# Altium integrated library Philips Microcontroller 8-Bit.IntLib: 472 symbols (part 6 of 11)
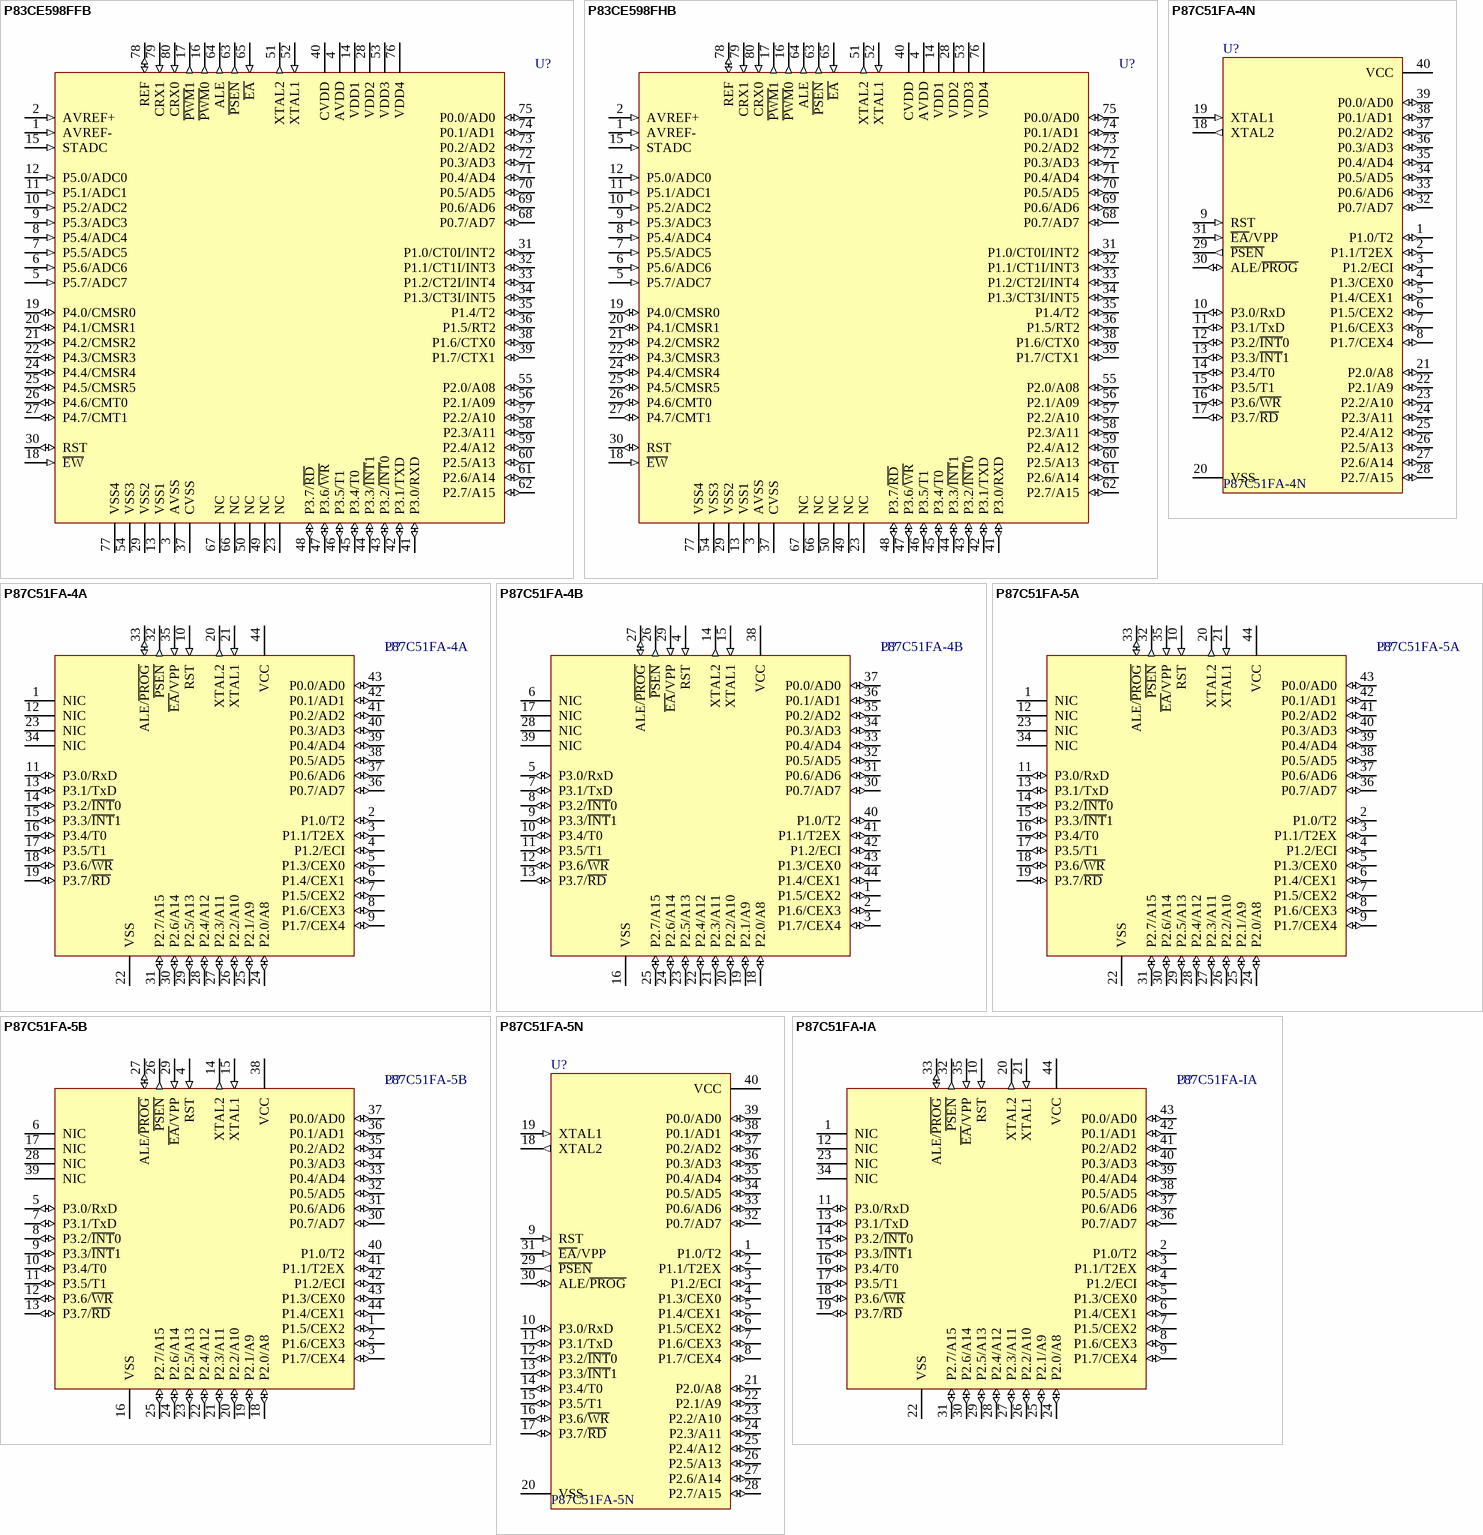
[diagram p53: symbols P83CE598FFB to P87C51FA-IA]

## P87C51FA-4A
designator U?
80C51 8-Bit Microcontroller Family: 256 B RAM, 8 kB OTP, 2.7V-5.5V, Low Power, High Speed
footprint SOT187-2_N (Leaded Chip Carrier, 44-Leads, Body 16.6x16.6mm, Pitch 1.27mm, IPC Medium Density)
footprint SOT187-2_L (Leaded Chip Carrier, 44-Leads, Body 16.6x16.6mm, Pitch 1.27mm, IPC High Density)
footprint SOT187-2_M (Leaded Chip Carrier, 44-Leads, Body 16.6x16.6mm, Pitch 1.27mm, IPC Low Density)
pins: 1 NIC, 2 P1.0/T2 (io), 3 P1.1/T2EX (io), 4 P1.2/ECI (io), 5 P1.3/CEX0 (io), 6 P1.4/CEX1 (io), 7 P1.5/CEX2 (io), 8 P1.6/CEX3 (io), 9 P1.7/CEX4 (io), 10 RST (in), 11 P3.0/RxD (io), 12 NIC, 13 P3.1/TxD (io), 14 P3.2/~{INT}0 (io), 15 P3.3/~{INT}1 (io), 16 P3.4/T0 (io), 17 P3.5/T1 (io), 18 P3.6/~{WR} (io), 19 P3.7/~{RD} (io), 20 XTAL2 (out), 21 XTAL1 (in), 22 VSS (power), 23 NIC, 24 P2.0/A8 (io), 25 P2.1/A9 (io), 26 P2.2/A10 (io), 27 P2.3/A11 (io), 28 P2.4/A12 (io), 29 P2.5/A13 (io), 30 P2.6/A14 (io), 31 P2.7/A15 (io), 32 ~{PSEN} (out), 33 ALE/~{PROG} (io), 34 NIC, 35 ~{EA}/VPP (in), 36 P0.7/AD7 (io), 37 P0.6/AD6 (io), 38 P0.5/AD5 (io), 39 P0.4/AD4 (io), 40 P0.3/AD3 (io), 41 P0.2/AD2 (io), 42 P0.1/AD1 (io), 43 P0.0/AD0 (io), 44 VCC (power)

## P87C51FA-4B
designator U?
80C51 8-Bit Microcontroller Family: 256 B RAM, 8 kB OTP, 2.7V-5.5V, Low Power, High Speed
footprint SOT307-2_N (QFP, 44-Leads, Body 10x10mm, Pitch 0.8mm, IPC Medium Density)
footprint SOT307-2_L (QFP, 44-Leads, Body 10x10mm, Pitch 0.8mm, IPC High Density)
footprint SOT307-2_M (QFP, 44-Leads, Body 10x10mm, Pitch 0.8mm, IPC Low Density)
pins: 1 P1.5/CEX2 (io), 2 P1.6/CEX3 (io), 3 P1.7/CEX4 (io), 4 RST (in), 5 P3.0/RxD (io), 6 NIC, 7 P3.1/TxD (io), 8 P3.2/~{INT}0 (io), 9 P3.3/~{INT}1 (io), 10 P3.4/T0 (io), 11 P3.5/T1 (io), 12 P3.6/~{WR} (io), 13 P3.7/~{RD} (io), 14 XTAL2 (out), 15 XTAL1 (in), 16 VSS (power), 17 NIC, 18 P2.0/A8 (io), 19 P2.1/A9 (io), 20 P2.2/A10 (io), 21 P2.3/A11 (io), 22 P2.4/A12 (io), 23 P2.5/A13 (io), 24 P2.6/A14 (io), 25 P2.7/A15 (io), 26 ~{PSEN} (out), 27 ALE/~{PROG} (io), 28 NIC, 29 ~{EA}/VPP (in), 30 P0.7/AD7 (io), 31 P0.6/AD6 (io), 32 P0.5/AD5 (io), 33 P0.4/AD4 (io), 34 P0.3/AD3 (io), 35 P0.2/AD2 (io), 36 P0.1/AD1 (io), 37 P0.0/AD0 (io), 38 VCC (power), 39 NIC, 40 P1.0/T2 (io), 41 P1.1/T2EX (io), 42 P1.2/ECI (io), 43 P1.3/CEX0 (io), 44 P1.4/CEX1 (io)

## P87C51FA-4N
designator U?
80C51 8-Bit Microcontroller Family: 256 B RAM, 8 kB OTP, 2.7V-5.5V, Low Power, High Speed
footprint SOT129-1 (DIP, Plastic; 40 Leads; Row Spacing 15.24 mm; Pitch 2.54 mm)
pins: 1 P1.0/T2 (io), 2 P1.1/T2EX (io), 3 P1.2/ECI (io), 4 P1.3/CEX0 (io), 5 P1.4/CEX1 (io), 6 P1.5/CEX2 (io), 7 P1.6/CEX3 (io), 8 P1.7/CEX4 (io), 9 RST (in), 10 P3.0/RxD (io), 11 P3.1/TxD (io), 12 P3.2/~{INT}0 (io), 13 P3.3/~{INT}1 (io), 14 P3.4/T0 (io), 15 P3.5/T1 (io), 16 P3.6/~{WR} (io), 17 P3.7/~{RD} (io), 18 XTAL2 (out), 19 XTAL1 (in), 20 VSS (power), 21 P2.0/A8 (io), 22 P2.1/A9 (io), 23 P2.2/A10 (io), 24 P2.3/A11 (io), 25 P2.4/A12 (io), 26 P2.5/A13 (io), 27 P2.6/A14 (io), 28 P2.7/A15 (io), 29 ~{PSEN} (out), 30 ALE/~{PROG} (io), 31 ~{EA}/VPP (in), 32 P0.7/AD7 (io), 33 P0.6/AD6 (io), 34 P0.5/AD5 (io), 35 P0.4/AD4 (io), 36 P0.3/AD3 (io), 37 P0.2/AD2 (io), 38 P0.1/AD1 (io), 39 P0.0/AD0 (io), 40 VCC (power)

## P87C51FA-5A
designator U?
80C51 8-Bit Microcontroller Family: 256 B RAM, 8 kB OTP, 2.7V-5.5V, Low Power, High Speed
footprint SOT187-2_N (Leaded Chip Carrier, 44-Leads, Body 16.6x16.6mm, Pitch 1.27mm, IPC Medium Density)
footprint SOT187-2_L (Leaded Chip Carrier, 44-Leads, Body 16.6x16.6mm, Pitch 1.27mm, IPC High Density)
footprint SOT187-2_M (Leaded Chip Carrier, 44-Leads, Body 16.6x16.6mm, Pitch 1.27mm, IPC Low Density)
pins: 1 NIC, 2 P1.0/T2 (io), 3 P1.1/T2EX (io), 4 P1.2/ECI (io), 5 P1.3/CEX0 (io), 6 P1.4/CEX1 (io), 7 P1.5/CEX2 (io), 8 P1.6/CEX3 (io), 9 P1.7/CEX4 (io), 10 RST (in), 11 P3.0/RxD (io), 12 NIC, 13 P3.1/TxD (io), 14 P3.2/~{INT}0 (io), 15 P3.3/~{INT}1 (io), 16 P3.4/T0 (io), 17 P3.5/T1 (io), 18 P3.6/~{WR} (io), 19 P3.7/~{RD} (io), 20 XTAL2 (out), 21 XTAL1 (in), 22 VSS (power), 23 NIC, 24 P2.0/A8 (io), 25 P2.1/A9 (io), 26 P2.2/A10 (io), 27 P2.3/A11 (io), 28 P2.4/A12 (io), 29 P2.5/A13 (io), 30 P2.6/A14 (io), 31 P2.7/A15 (io), 32 ~{PSEN} (out), 33 ALE/~{PROG} (io), 34 NIC, 35 ~{EA}/VPP (in), 36 P0.7/AD7 (io), 37 P0.6/AD6 (io), 38 P0.5/AD5 (io), 39 P0.4/AD4 (io), 40 P0.3/AD3 (io), 41 P0.2/AD2 (io), 42 P0.1/AD1 (io), 43 P0.0/AD0 (io), 44 VCC (power)

## P87C51FA-5B
designator U?
80C51 8-Bit Microcontroller Family: 256 B RAM, 8 kB OTP, 2.7V-5.5V, Low Power, High Speed
footprint SOT307-2_N (QFP, 44-Leads, Body 10x10mm, Pitch 0.8mm, IPC Medium Density)
footprint SOT307-2_L (QFP, 44-Leads, Body 10x10mm, Pitch 0.8mm, IPC High Density)
footprint SOT307-2_M (QFP, 44-Leads, Body 10x10mm, Pitch 0.8mm, IPC Low Density)
pins: 1 P1.5/CEX2 (io), 2 P1.6/CEX3 (io), 3 P1.7/CEX4 (io), 4 RST (in), 5 P3.0/RxD (io), 6 NIC, 7 P3.1/TxD (io), 8 P3.2/~{INT}0 (io), 9 P3.3/~{INT}1 (io), 10 P3.4/T0 (io), 11 P3.5/T1 (io), 12 P3.6/~{WR} (io), 13 P3.7/~{RD} (io), 14 XTAL2 (out), 15 XTAL1 (in), 16 VSS (power), 17 NIC, 18 P2.0/A8 (io), 19 P2.1/A9 (io), 20 P2.2/A10 (io), 21 P2.3/A11 (io), 22 P2.4/A12 (io), 23 P2.5/A13 (io), 24 P2.6/A14 (io), 25 P2.7/A15 (io), 26 ~{PSEN} (out), 27 ALE/~{PROG} (io), 28 NIC, 29 ~{EA}/VPP (in), 30 P0.7/AD7 (io), 31 P0.6/AD6 (io), 32 P0.5/AD5 (io), 33 P0.4/AD4 (io), 34 P0.3/AD3 (io), 35 P0.2/AD2 (io), 36 P0.1/AD1 (io), 37 P0.0/AD0 (io), 38 VCC (power), 39 NIC, 40 P1.0/T2 (io), 41 P1.1/T2EX (io), 42 P1.2/ECI (io), 43 P1.3/CEX0 (io), 44 P1.4/CEX1 (io)

## P87C51FA-5N
designator U?
80C51 8-Bit Microcontroller Family: 256 B RAM, 8 kB OTP, 2.7V-5.5V, Low Power, High Speed
footprint SOT129-1 (DIP, Plastic; 40 Leads; Row Spacing 15.24 mm; Pitch 2.54 mm)
pins: 1 P1.0/T2 (io), 2 P1.1/T2EX (io), 3 P1.2/ECI (io), 4 P1.3/CEX0 (io), 5 P1.4/CEX1 (io), 6 P1.5/CEX2 (io), 7 P1.6/CEX3 (io), 8 P1.7/CEX4 (io), 9 RST (in), 10 P3.0/RxD (io), 11 P3.1/TxD (io), 12 P3.2/~{INT}0 (io), 13 P3.3/~{INT}1 (io), 14 P3.4/T0 (io), 15 P3.5/T1 (io), 16 P3.6/~{WR} (io), 17 P3.7/~{RD} (io), 18 XTAL2 (out), 19 XTAL1 (in), 20 VSS (power), 21 P2.0/A8 (io), 22 P2.1/A9 (io), 23 P2.2/A10 (io), 24 P2.3/A11 (io), 25 P2.4/A12 (io), 26 P2.5/A13 (io), 27 P2.6/A14 (io), 28 P2.7/A15 (io), 29 ~{PSEN} (out), 30 ALE/~{PROG} (io), 31 ~{EA}/VPP (in), 32 P0.7/AD7 (io), 33 P0.6/AD6 (io), 34 P0.5/AD5 (io), 35 P0.4/AD4 (io), 36 P0.3/AD3 (io), 37 P0.2/AD2 (io), 38 P0.1/AD1 (io), 39 P0.0/AD0 (io), 40 VCC (power)

## P87C51FA-IA
designator U?
80C51 8-Bit Microcontroller Family: 256 B RAM, 8 kB OTP, 5V, Low Power, High Speed
footprint SOT187-2_N (Leaded Chip Carrier, 44-Leads, Body 16.6x16.6mm, Pitch 1.27mm, IPC Medium Density)
footprint SOT187-2_L (Leaded Chip Carrier, 44-Leads, Body 16.6x16.6mm, Pitch 1.27mm, IPC High Density)
footprint SOT187-2_M (Leaded Chip Carrier, 44-Leads, Body 16.6x16.6mm, Pitch 1.27mm, IPC Low Density)
pins: 1 NIC, 2 P1.0/T2 (io), 3 P1.1/T2EX (io), 4 P1.2/ECI (io), 5 P1.3/CEX0 (io), 6 P1.4/CEX1 (io), 7 P1.5/CEX2 (io), 8 P1.6/CEX3 (io), 9 P1.7/CEX4 (io), 10 RST (in), 11 P3.0/RxD (io), 12 NIC, 13 P3.1/TxD (io), 14 P3.2/~{INT}0 (io), 15 P3.3/~{INT}1 (io), 16 P3.4/T0 (io), 17 P3.5/T1 (io), 18 P3.6/~{WR} (io), 19 P3.7/~{RD} (io), 20 XTAL2 (out), 21 XTAL1 (in), 22 VSS (power), 23 NIC, 24 P2.0/A8 (io), 25 P2.1/A9 (io), 26 P2.2/A10 (io), 27 P2.3/A11 (io), 28 P2.4/A12 (io), 29 P2.5/A13 (io), 30 P2.6/A14 (io), 31 P2.7/A15 (io), 32 ~{PSEN} (out), 33 ALE/~{PROG} (io), 34 NIC, 35 ~{EA}/VPP (in), 36 P0.7/AD7 (io), 37 P0.6/AD6 (io), 38 P0.5/AD5 (io), 39 P0.4/AD4 (io), 40 P0.3/AD3 (io), 41 P0.2/AD2 (io), 42 P0.1/AD1 (io), 43 P0.0/AD0 (io), 44 VCC (power)

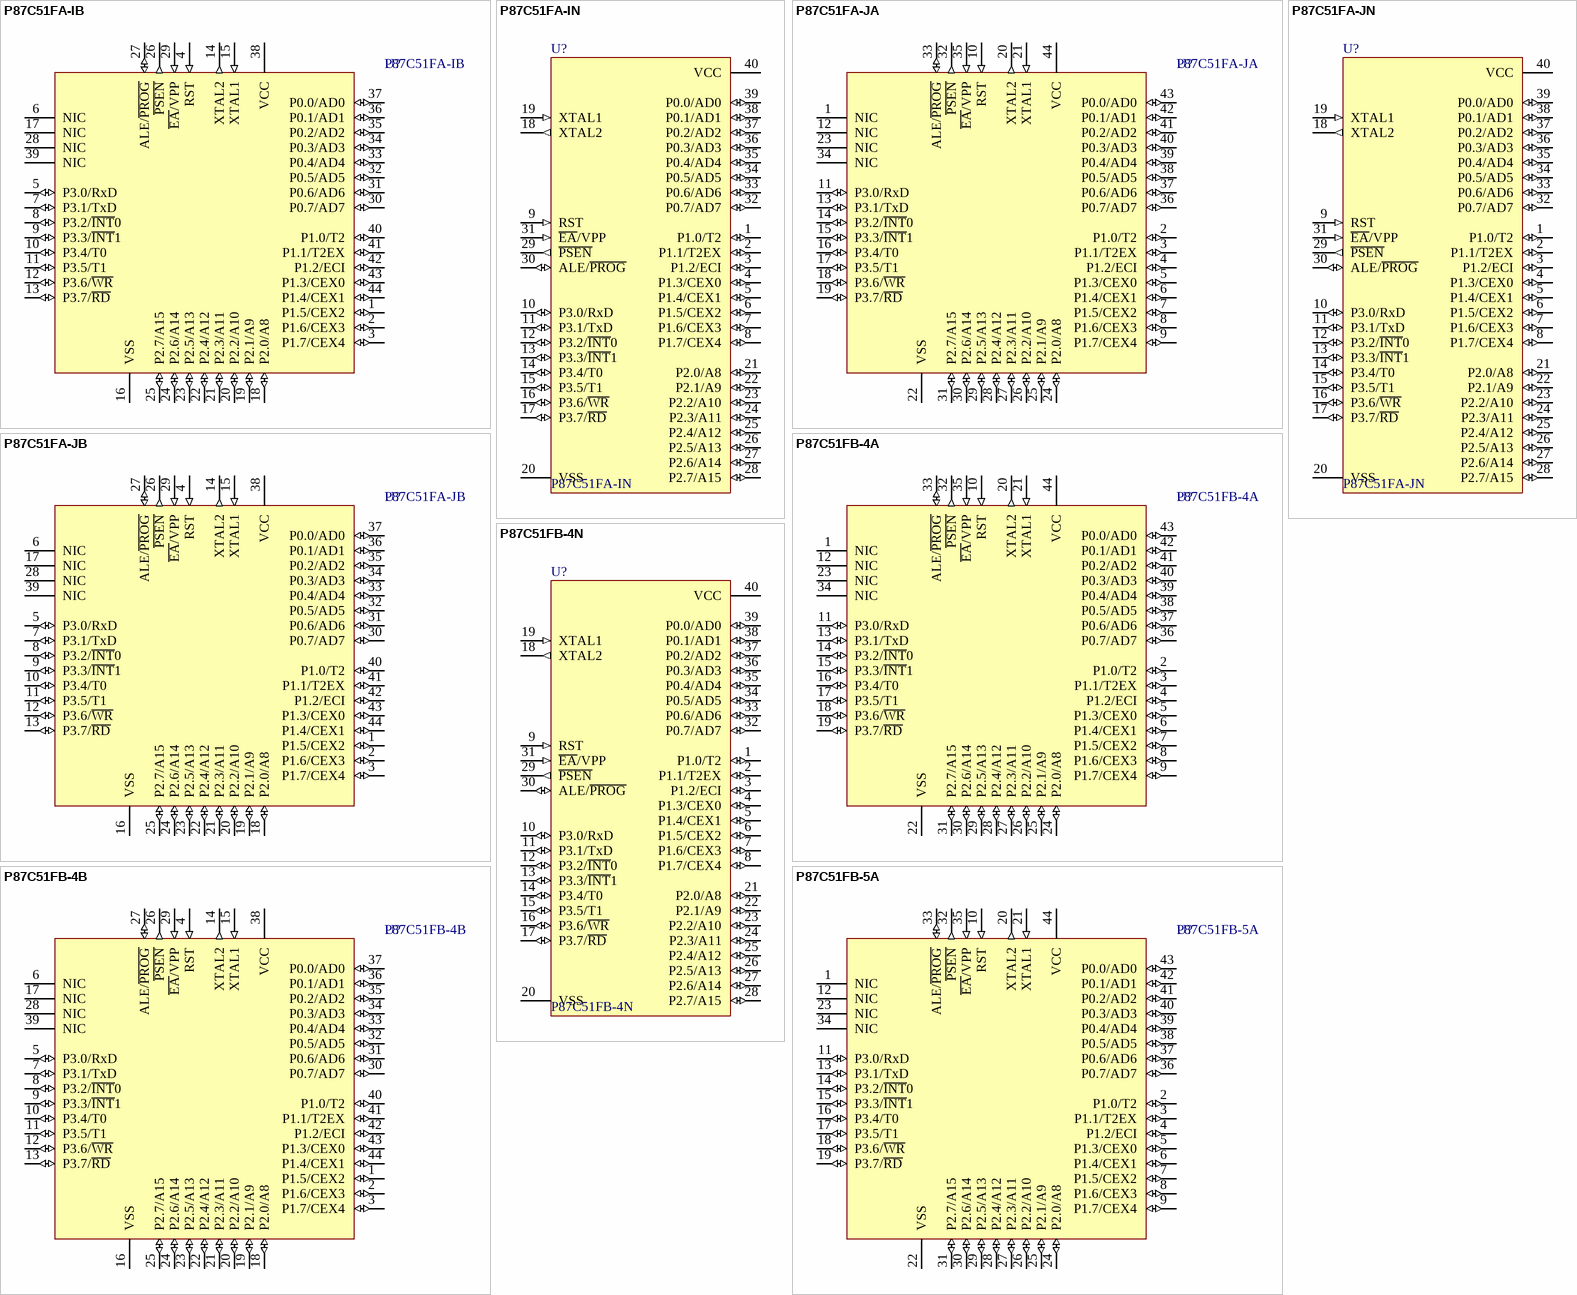
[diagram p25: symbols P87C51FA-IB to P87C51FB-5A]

## P87C51FA-IB
designator U?
80C51 8-Bit Microcontroller Family: 256 B RAM, 8 kB OTP, 5V, Low Power, High Speed
footprint SOT307-2_N (QFP, 44-Leads, Body 10x10mm, Pitch 0.8mm, IPC Medium Density)
footprint SOT307-2_L (QFP, 44-Leads, Body 10x10mm, Pitch 0.8mm, IPC High Density)
footprint SOT307-2_M (QFP, 44-Leads, Body 10x10mm, Pitch 0.8mm, IPC Low Density)
pins: 1 P1.5/CEX2 (io), 2 P1.6/CEX3 (io), 3 P1.7/CEX4 (io), 4 RST (in), 5 P3.0/RxD (io), 6 NIC, 7 P3.1/TxD (io), 8 P3.2/~{INT}0 (io), 9 P3.3/~{INT}1 (io), 10 P3.4/T0 (io), 11 P3.5/T1 (io), 12 P3.6/~{WR} (io), 13 P3.7/~{RD} (io), 14 XTAL2 (out), 15 XTAL1 (in), 16 VSS (power), 17 NIC, 18 P2.0/A8 (io), 19 P2.1/A9 (io), 20 P2.2/A10 (io), 21 P2.3/A11 (io), 22 P2.4/A12 (io), 23 P2.5/A13 (io), 24 P2.6/A14 (io), 25 P2.7/A15 (io), 26 ~{PSEN} (out), 27 ALE/~{PROG} (io), 28 NIC, 29 ~{EA}/VPP (in), 30 P0.7/AD7 (io), 31 P0.6/AD6 (io), 32 P0.5/AD5 (io), 33 P0.4/AD4 (io), 34 P0.3/AD3 (io), 35 P0.2/AD2 (io), 36 P0.1/AD1 (io), 37 P0.0/AD0 (io), 38 VCC (power), 39 NIC, 40 P1.0/T2 (io), 41 P1.1/T2EX (io), 42 P1.2/ECI (io), 43 P1.3/CEX0 (io), 44 P1.4/CEX1 (io)

## P87C51FA-IN
designator U?
80C51 8-Bit Microcontroller Family: 256 B RAM, 8 kB OTP, 5V, Low Power, High Speed
footprint SOT129-1 (DIP, Plastic; 40 Leads; Row Spacing 15.24 mm; Pitch 2.54 mm)
pins: 1 P1.0/T2 (io), 2 P1.1/T2EX (io), 3 P1.2/ECI (io), 4 P1.3/CEX0 (io), 5 P1.4/CEX1 (io), 6 P1.5/CEX2 (io), 7 P1.6/CEX3 (io), 8 P1.7/CEX4 (io), 9 RST (in), 10 P3.0/RxD (io), 11 P3.1/TxD (io), 12 P3.2/~{INT}0 (io), 13 P3.3/~{INT}1 (io), 14 P3.4/T0 (io), 15 P3.5/T1 (io), 16 P3.6/~{WR} (io), 17 P3.7/~{RD} (io), 18 XTAL2 (out), 19 XTAL1 (in), 20 VSS (power), 21 P2.0/A8 (io), 22 P2.1/A9 (io), 23 P2.2/A10 (io), 24 P2.3/A11 (io), 25 P2.4/A12 (io), 26 P2.5/A13 (io), 27 P2.6/A14 (io), 28 P2.7/A15 (io), 29 ~{PSEN} (out), 30 ALE/~{PROG} (io), 31 ~{EA}/VPP (in), 32 P0.7/AD7 (io), 33 P0.6/AD6 (io), 34 P0.5/AD5 (io), 35 P0.4/AD4 (io), 36 P0.3/AD3 (io), 37 P0.2/AD2 (io), 38 P0.1/AD1 (io), 39 P0.0/AD0 (io), 40 VCC (power)

## P87C51FA-JA
designator U?
80C51 8-Bit Microcontroller Family: 256 B RAM, 8 kB OTP, 5V, Low Power, High Speed
footprint SOT187-2_N (Leaded Chip Carrier, 44-Leads, Body 16.6x16.6mm, Pitch 1.27mm, IPC Medium Density)
footprint SOT187-2_L (Leaded Chip Carrier, 44-Leads, Body 16.6x16.6mm, Pitch 1.27mm, IPC High Density)
footprint SOT187-2_M (Leaded Chip Carrier, 44-Leads, Body 16.6x16.6mm, Pitch 1.27mm, IPC Low Density)
pins: 1 NIC, 2 P1.0/T2 (io), 3 P1.1/T2EX (io), 4 P1.2/ECI (io), 5 P1.3/CEX0 (io), 6 P1.4/CEX1 (io), 7 P1.5/CEX2 (io), 8 P1.6/CEX3 (io), 9 P1.7/CEX4 (io), 10 RST (in), 11 P3.0/RxD (io), 12 NIC, 13 P3.1/TxD (io), 14 P3.2/~{INT}0 (io), 15 P3.3/~{INT}1 (io), 16 P3.4/T0 (io), 17 P3.5/T1 (io), 18 P3.6/~{WR} (io), 19 P3.7/~{RD} (io), 20 XTAL2 (out), 21 XTAL1 (in), 22 VSS (power), 23 NIC, 24 P2.0/A8 (io), 25 P2.1/A9 (io), 26 P2.2/A10 (io), 27 P2.3/A11 (io), 28 P2.4/A12 (io), 29 P2.5/A13 (io), 30 P2.6/A14 (io), 31 P2.7/A15 (io), 32 ~{PSEN} (out), 33 ALE/~{PROG} (io), 34 NIC, 35 ~{EA}/VPP (in), 36 P0.7/AD7 (io), 37 P0.6/AD6 (io), 38 P0.5/AD5 (io), 39 P0.4/AD4 (io), 40 P0.3/AD3 (io), 41 P0.2/AD2 (io), 42 P0.1/AD1 (io), 43 P0.0/AD0 (io), 44 VCC (power)

## P87C51FA-JB
designator U?
80C51 8-Bit Microcontroller Family: 256 B RAM, 8 kB OTP, 5V, Low Power, High Speed
footprint SOT307-2_N (QFP, 44-Leads, Body 10x10mm, Pitch 0.8mm, IPC Medium Density)
footprint SOT307-2_L (QFP, 44-Leads, Body 10x10mm, Pitch 0.8mm, IPC High Density)
footprint SOT307-2_M (QFP, 44-Leads, Body 10x10mm, Pitch 0.8mm, IPC Low Density)
pins: 1 P1.5/CEX2 (io), 2 P1.6/CEX3 (io), 3 P1.7/CEX4 (io), 4 RST (in), 5 P3.0/RxD (io), 6 NIC, 7 P3.1/TxD (io), 8 P3.2/~{INT}0 (io), 9 P3.3/~{INT}1 (io), 10 P3.4/T0 (io), 11 P3.5/T1 (io), 12 P3.6/~{WR} (io), 13 P3.7/~{RD} (io), 14 XTAL2 (out), 15 XTAL1 (in), 16 VSS (power), 17 NIC, 18 P2.0/A8 (io), 19 P2.1/A9 (io), 20 P2.2/A10 (io), 21 P2.3/A11 (io), 22 P2.4/A12 (io), 23 P2.5/A13 (io), 24 P2.6/A14 (io), 25 P2.7/A15 (io), 26 ~{PSEN} (out), 27 ALE/~{PROG} (io), 28 NIC, 29 ~{EA}/VPP (in), 30 P0.7/AD7 (io), 31 P0.6/AD6 (io), 32 P0.5/AD5 (io), 33 P0.4/AD4 (io), 34 P0.3/AD3 (io), 35 P0.2/AD2 (io), 36 P0.1/AD1 (io), 37 P0.0/AD0 (io), 38 VCC (power), 39 NIC, 40 P1.0/T2 (io), 41 P1.1/T2EX (io), 42 P1.2/ECI (io), 43 P1.3/CEX0 (io), 44 P1.4/CEX1 (io)

## P87C51FA-JN
designator U?
80C51 8-Bit Microcontroller Family: 256 B RAM, 8 kB OTP, 5V, Low Power, High Speed
footprint SOT129-1 (DIP, Plastic; 40 Leads; Row Spacing 15.24 mm; Pitch 2.54 mm)
pins: 1 P1.0/T2 (io), 2 P1.1/T2EX (io), 3 P1.2/ECI (io), 4 P1.3/CEX0 (io), 5 P1.4/CEX1 (io), 6 P1.5/CEX2 (io), 7 P1.6/CEX3 (io), 8 P1.7/CEX4 (io), 9 RST (in), 10 P3.0/RxD (io), 11 P3.1/TxD (io), 12 P3.2/~{INT}0 (io), 13 P3.3/~{INT}1 (io), 14 P3.4/T0 (io), 15 P3.5/T1 (io), 16 P3.6/~{WR} (io), 17 P3.7/~{RD} (io), 18 XTAL2 (out), 19 XTAL1 (in), 20 VSS (power), 21 P2.0/A8 (io), 22 P2.1/A9 (io), 23 P2.2/A10 (io), 24 P2.3/A11 (io), 25 P2.4/A12 (io), 26 P2.5/A13 (io), 27 P2.6/A14 (io), 28 P2.7/A15 (io), 29 ~{PSEN} (out), 30 ALE/~{PROG} (io), 31 ~{EA}/VPP (in), 32 P0.7/AD7 (io), 33 P0.6/AD6 (io), 34 P0.5/AD5 (io), 35 P0.4/AD4 (io), 36 P0.3/AD3 (io), 37 P0.2/AD2 (io), 38 P0.1/AD1 (io), 39 P0.0/AD0 (io), 40 VCC (power)

## P87C51FB-4A
designator U?
80C51 8-Bit Microcontroller Family: 256 B RAM, 16 kB OTP, 2.7V-5.5V, Low Power, High Speed
footprint SOT187-2_N (Leaded Chip Carrier, 44-Leads, Body 16.6x16.6mm, Pitch 1.27mm, IPC Medium Density)
footprint SOT187-2_L (Leaded Chip Carrier, 44-Leads, Body 16.6x16.6mm, Pitch 1.27mm, IPC High Density)
footprint SOT187-2_M (Leaded Chip Carrier, 44-Leads, Body 16.6x16.6mm, Pitch 1.27mm, IPC Low Density)
pins: 1 NIC, 2 P1.0/T2 (io), 3 P1.1/T2EX (io), 4 P1.2/ECI (io), 5 P1.3/CEX0 (io), 6 P1.4/CEX1 (io), 7 P1.5/CEX2 (io), 8 P1.6/CEX3 (io), 9 P1.7/CEX4 (io), 10 RST (in), 11 P3.0/RxD (io), 12 NIC, 13 P3.1/TxD (io), 14 P3.2/~{INT}0 (io), 15 P3.3/~{INT}1 (io), 16 P3.4/T0 (io), 17 P3.5/T1 (io), 18 P3.6/~{WR} (io), 19 P3.7/~{RD} (io), 20 XTAL2 (out), 21 XTAL1 (in), 22 VSS (power), 23 NIC, 24 P2.0/A8 (io), 25 P2.1/A9 (io), 26 P2.2/A10 (io), 27 P2.3/A11 (io), 28 P2.4/A12 (io), 29 P2.5/A13 (io), 30 P2.6/A14 (io), 31 P2.7/A15 (io), 32 ~{PSEN} (out), 33 ALE/~{PROG} (io), 34 NIC, 35 ~{EA}/VPP (in), 36 P0.7/AD7 (io), 37 P0.6/AD6 (io), 38 P0.5/AD5 (io), 39 P0.4/AD4 (io), 40 P0.3/AD3 (io), 41 P0.2/AD2 (io), 42 P0.1/AD1 (io), 43 P0.0/AD0 (io), 44 VCC (power)

## P87C51FB-4B
designator U?
80C51 8-Bit Microcontroller Family: 256 B RAM, 16 kB OTP, 2.7V-5.5V, Low Power, High Speed
footprint SOT307-2_N (QFP, 44-Leads, Body 10x10mm, Pitch 0.8mm, IPC Medium Density)
footprint SOT307-2_L (QFP, 44-Leads, Body 10x10mm, Pitch 0.8mm, IPC High Density)
footprint SOT307-2_M (QFP, 44-Leads, Body 10x10mm, Pitch 0.8mm, IPC Low Density)
pins: 1 P1.5/CEX2 (io), 2 P1.6/CEX3 (io), 3 P1.7/CEX4 (io), 4 RST (in), 5 P3.0/RxD (io), 6 NIC, 7 P3.1/TxD (io), 8 P3.2/~{INT}0 (io), 9 P3.3/~{INT}1 (io), 10 P3.4/T0 (io), 11 P3.5/T1 (io), 12 P3.6/~{WR} (io), 13 P3.7/~{RD} (io), 14 XTAL2 (out), 15 XTAL1 (in), 16 VSS (power), 17 NIC, 18 P2.0/A8 (io), 19 P2.1/A9 (io), 20 P2.2/A10 (io), 21 P2.3/A11 (io), 22 P2.4/A12 (io), 23 P2.5/A13 (io), 24 P2.6/A14 (io), 25 P2.7/A15 (io), 26 ~{PSEN} (out), 27 ALE/~{PROG} (io), 28 NIC, 29 ~{EA}/VPP (in), 30 P0.7/AD7 (io), 31 P0.6/AD6 (io), 32 P0.5/AD5 (io), 33 P0.4/AD4 (io), 34 P0.3/AD3 (io), 35 P0.2/AD2 (io), 36 P0.1/AD1 (io), 37 P0.0/AD0 (io), 38 VCC (power), 39 NIC, 40 P1.0/T2 (io), 41 P1.1/T2EX (io), 42 P1.2/ECI (io), 43 P1.3/CEX0 (io), 44 P1.4/CEX1 (io)

## P87C51FB-4N
designator U?
80C51 8-Bit Microcontroller Family: 256 B RAM, 16 kB OTP, 2.7V-5.5V, Low Power, High Speed
footprint SOT129-1 (DIP, Plastic; 40 Leads; Row Spacing 15.24 mm; Pitch 2.54 mm)
pins: 1 P1.0/T2 (io), 2 P1.1/T2EX (io), 3 P1.2/ECI (io), 4 P1.3/CEX0 (io), 5 P1.4/CEX1 (io), 6 P1.5/CEX2 (io), 7 P1.6/CEX3 (io), 8 P1.7/CEX4 (io), 9 RST (in), 10 P3.0/RxD (io), 11 P3.1/TxD (io), 12 P3.2/~{INT}0 (io), 13 P3.3/~{INT}1 (io), 14 P3.4/T0 (io), 15 P3.5/T1 (io), 16 P3.6/~{WR} (io), 17 P3.7/~{RD} (io), 18 XTAL2 (out), 19 XTAL1 (in), 20 VSS (power), 21 P2.0/A8 (io), 22 P2.1/A9 (io), 23 P2.2/A10 (io), 24 P2.3/A11 (io), 25 P2.4/A12 (io), 26 P2.5/A13 (io), 27 P2.6/A14 (io), 28 P2.7/A15 (io), 29 ~{PSEN} (out), 30 ALE/~{PROG} (io), 31 ~{EA}/VPP (in), 32 P0.7/AD7 (io), 33 P0.6/AD6 (io), 34 P0.5/AD5 (io), 35 P0.4/AD4 (io), 36 P0.3/AD3 (io), 37 P0.2/AD2 (io), 38 P0.1/AD1 (io), 39 P0.0/AD0 (io), 40 VCC (power)

## P87C51FB-5A
designator U?
80C51 8-Bit Microcontroller Family: 256 B RAM, 16 kB OTP, 2.7V-5.5V, Low Power, High Speed
footprint SOT187-2_N (Leaded Chip Carrier, 44-Leads, Body 16.6x16.6mm, Pitch 1.27mm, IPC Medium Density)
footprint SOT187-2_L (Leaded Chip Carrier, 44-Leads, Body 16.6x16.6mm, Pitch 1.27mm, IPC High Density)
footprint SOT187-2_M (Leaded Chip Carrier, 44-Leads, Body 16.6x16.6mm, Pitch 1.27mm, IPC Low Density)
pins: 1 NIC, 2 P1.0/T2 (io), 3 P1.1/T2EX (io), 4 P1.2/ECI (io), 5 P1.3/CEX0 (io), 6 P1.4/CEX1 (io), 7 P1.5/CEX2 (io), 8 P1.6/CEX3 (io), 9 P1.7/CEX4 (io), 10 RST (in), 11 P3.0/RxD (io), 12 NIC, 13 P3.1/TxD (io), 14 P3.2/~{INT}0 (io), 15 P3.3/~{INT}1 (io), 16 P3.4/T0 (io), 17 P3.5/T1 (io), 18 P3.6/~{WR} (io), 19 P3.7/~{RD} (io), 20 XTAL2 (out), 21 XTAL1 (in), 22 VSS (power), 23 NIC, 24 P2.0/A8 (io), 25 P2.1/A9 (io), 26 P2.2/A10 (io), 27 P2.3/A11 (io), 28 P2.4/A12 (io), 29 P2.5/A13 (io), 30 P2.6/A14 (io), 31 P2.7/A15 (io), 32 ~{PSEN} (out), 33 ALE/~{PROG} (io), 34 NIC, 35 ~{EA}/VPP (in), 36 P0.7/AD7 (io), 37 P0.6/AD6 (io), 38 P0.5/AD5 (io), 39 P0.4/AD4 (io), 40 P0.3/AD3 (io), 41 P0.2/AD2 (io), 42 P0.1/AD1 (io), 43 P0.0/AD0 (io), 44 VCC (power)

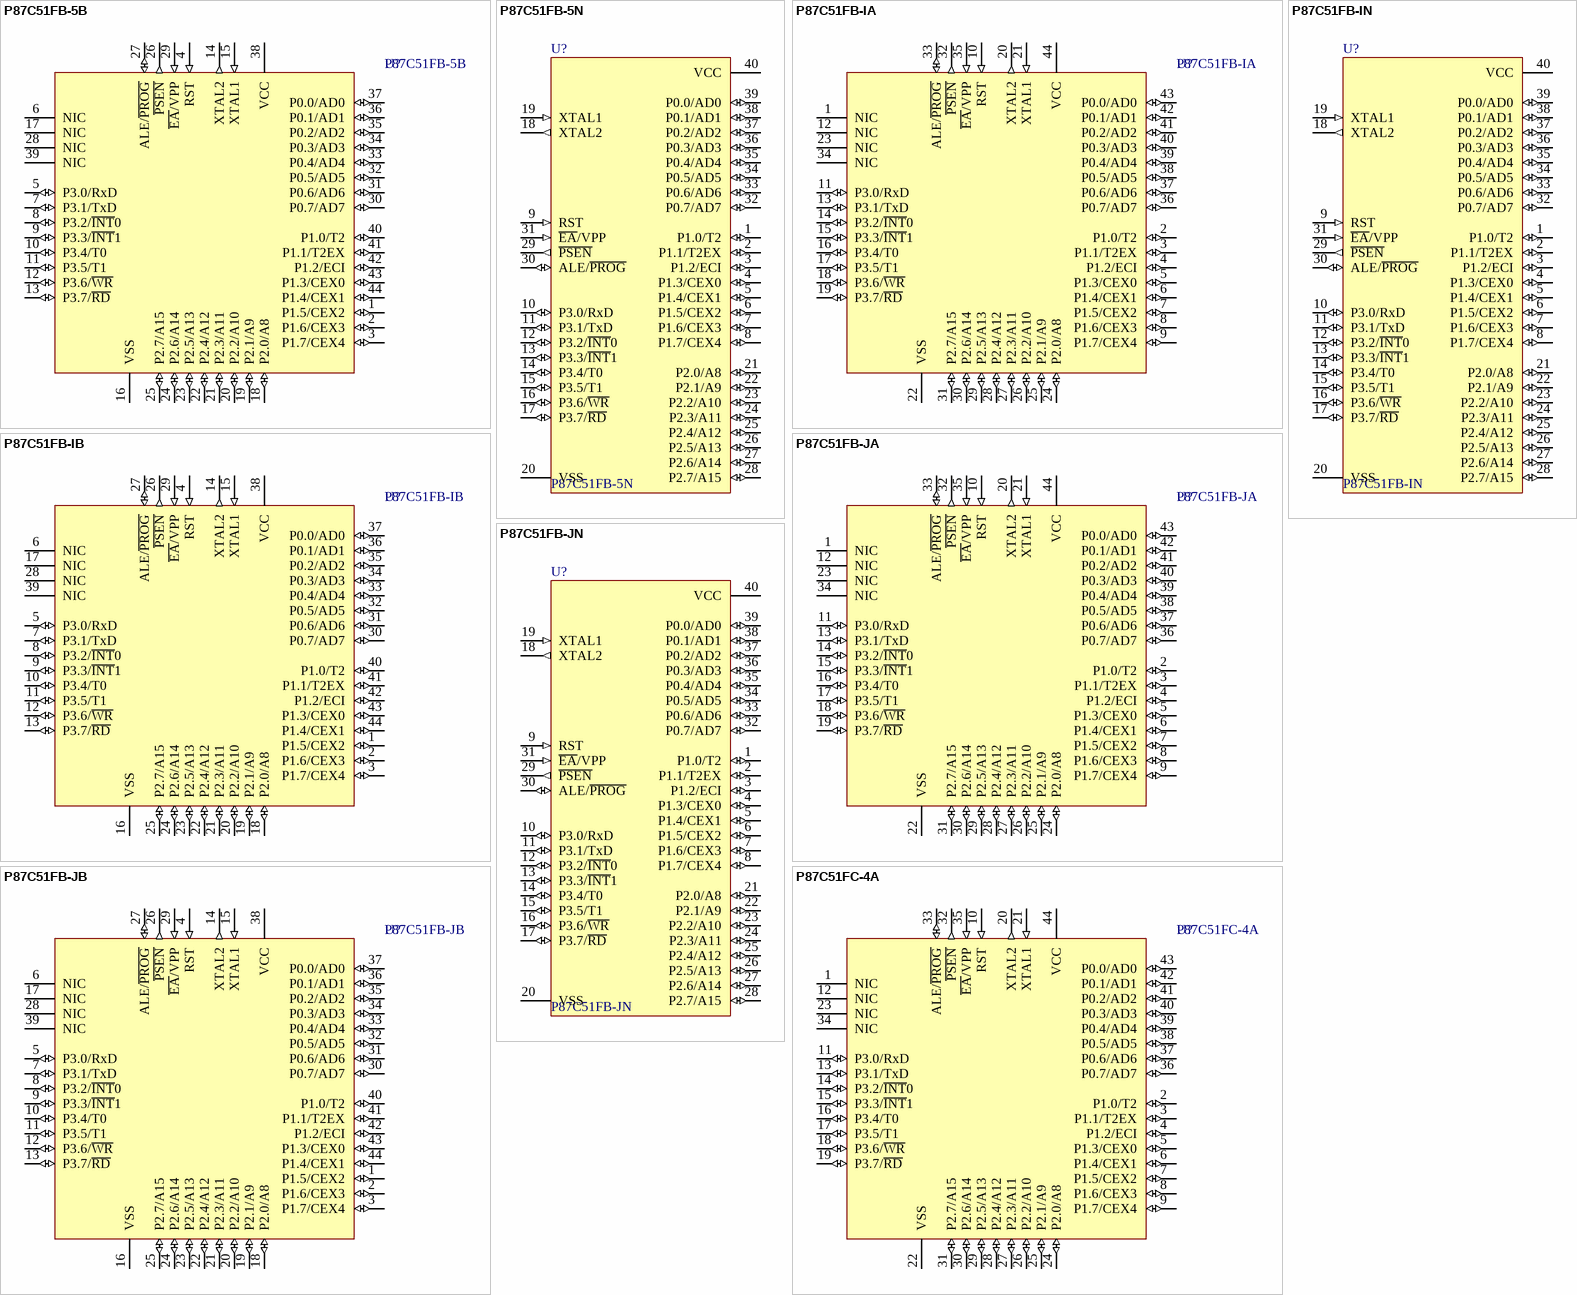
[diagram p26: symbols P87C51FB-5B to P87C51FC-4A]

## P87C51FB-5B
designator U?
80C51 8-Bit Microcontroller Family: 256 B RAM, 16 kB OTP, 2.7V-5.5V, Low Power, High Speed
footprint SOT307-2_N (QFP, 44-Leads, Body 10x10mm, Pitch 0.8mm, IPC Medium Density)
footprint SOT307-2_L (QFP, 44-Leads, Body 10x10mm, Pitch 0.8mm, IPC High Density)
footprint SOT307-2_M (QFP, 44-Leads, Body 10x10mm, Pitch 0.8mm, IPC Low Density)
pins: 1 P1.5/CEX2 (io), 2 P1.6/CEX3 (io), 3 P1.7/CEX4 (io), 4 RST (in), 5 P3.0/RxD (io), 6 NIC, 7 P3.1/TxD (io), 8 P3.2/~{INT}0 (io), 9 P3.3/~{INT}1 (io), 10 P3.4/T0 (io), 11 P3.5/T1 (io), 12 P3.6/~{WR} (io), 13 P3.7/~{RD} (io), 14 XTAL2 (out), 15 XTAL1 (in), 16 VSS (power), 17 NIC, 18 P2.0/A8 (io), 19 P2.1/A9 (io), 20 P2.2/A10 (io), 21 P2.3/A11 (io), 22 P2.4/A12 (io), 23 P2.5/A13 (io), 24 P2.6/A14 (io), 25 P2.7/A15 (io), 26 ~{PSEN} (out), 27 ALE/~{PROG} (io), 28 NIC, 29 ~{EA}/VPP (in), 30 P0.7/AD7 (io), 31 P0.6/AD6 (io), 32 P0.5/AD5 (io), 33 P0.4/AD4 (io), 34 P0.3/AD3 (io), 35 P0.2/AD2 (io), 36 P0.1/AD1 (io), 37 P0.0/AD0 (io), 38 VCC (power), 39 NIC, 40 P1.0/T2 (io), 41 P1.1/T2EX (io), 42 P1.2/ECI (io), 43 P1.3/CEX0 (io), 44 P1.4/CEX1 (io)

## P87C51FB-5N
designator U?
80C51 8-Bit Microcontroller Family: 256 B RAM, 16 kB OTP, 2.7V-5.5V, Low Power, High Speed
footprint SOT129-1 (DIP, Plastic; 40 Leads; Row Spacing 15.24 mm; Pitch 2.54 mm)
pins: 1 P1.0/T2 (io), 2 P1.1/T2EX (io), 3 P1.2/ECI (io), 4 P1.3/CEX0 (io), 5 P1.4/CEX1 (io), 6 P1.5/CEX2 (io), 7 P1.6/CEX3 (io), 8 P1.7/CEX4 (io), 9 RST (in), 10 P3.0/RxD (io), 11 P3.1/TxD (io), 12 P3.2/~{INT}0 (io), 13 P3.3/~{INT}1 (io), 14 P3.4/T0 (io), 15 P3.5/T1 (io), 16 P3.6/~{WR} (io), 17 P3.7/~{RD} (io), 18 XTAL2 (out), 19 XTAL1 (in), 20 VSS (power), 21 P2.0/A8 (io), 22 P2.1/A9 (io), 23 P2.2/A10 (io), 24 P2.3/A11 (io), 25 P2.4/A12 (io), 26 P2.5/A13 (io), 27 P2.6/A14 (io), 28 P2.7/A15 (io), 29 ~{PSEN} (out), 30 ALE/~{PROG} (io), 31 ~{EA}/VPP (in), 32 P0.7/AD7 (io), 33 P0.6/AD6 (io), 34 P0.5/AD5 (io), 35 P0.4/AD4 (io), 36 P0.3/AD3 (io), 37 P0.2/AD2 (io), 38 P0.1/AD1 (io), 39 P0.0/AD0 (io), 40 VCC (power)

## P87C51FB-IA
designator U?
80C51 8-Bit Microcontroller Family: 256 B RAM, 16 kB OTP, 5V, Low Power, High Speed
footprint SOT187-2_N (Leaded Chip Carrier, 44-Leads, Body 16.6x16.6mm, Pitch 1.27mm, IPC Medium Density)
footprint SOT187-2_L (Leaded Chip Carrier, 44-Leads, Body 16.6x16.6mm, Pitch 1.27mm, IPC High Density)
footprint SOT187-2_M (Leaded Chip Carrier, 44-Leads, Body 16.6x16.6mm, Pitch 1.27mm, IPC Low Density)
pins: 1 NIC, 2 P1.0/T2 (io), 3 P1.1/T2EX (io), 4 P1.2/ECI (io), 5 P1.3/CEX0 (io), 6 P1.4/CEX1 (io), 7 P1.5/CEX2 (io), 8 P1.6/CEX3 (io), 9 P1.7/CEX4 (io), 10 RST (in), 11 P3.0/RxD (io), 12 NIC, 13 P3.1/TxD (io), 14 P3.2/~{INT}0 (io), 15 P3.3/~{INT}1 (io), 16 P3.4/T0 (io), 17 P3.5/T1 (io), 18 P3.6/~{WR} (io), 19 P3.7/~{RD} (io), 20 XTAL2 (out), 21 XTAL1 (in), 22 VSS (power), 23 NIC, 24 P2.0/A8 (io), 25 P2.1/A9 (io), 26 P2.2/A10 (io), 27 P2.3/A11 (io), 28 P2.4/A12 (io), 29 P2.5/A13 (io), 30 P2.6/A14 (io), 31 P2.7/A15 (io), 32 ~{PSEN} (out), 33 ALE/~{PROG} (io), 34 NIC, 35 ~{EA}/VPP (in), 36 P0.7/AD7 (io), 37 P0.6/AD6 (io), 38 P0.5/AD5 (io), 39 P0.4/AD4 (io), 40 P0.3/AD3 (io), 41 P0.2/AD2 (io), 42 P0.1/AD1 (io), 43 P0.0/AD0 (io), 44 VCC (power)

## P87C51FB-IB
designator U?
80C51 8-Bit Microcontroller Family: 256 B RAM, 16 kB OTP, 5V, Low Power, High Speed
footprint SOT307-2_N (QFP, 44-Leads, Body 10x10mm, Pitch 0.8mm, IPC Medium Density)
footprint SOT307-2_L (QFP, 44-Leads, Body 10x10mm, Pitch 0.8mm, IPC High Density)
footprint SOT307-2_M (QFP, 44-Leads, Body 10x10mm, Pitch 0.8mm, IPC Low Density)
pins: 1 P1.5/CEX2 (io), 2 P1.6/CEX3 (io), 3 P1.7/CEX4 (io), 4 RST (in), 5 P3.0/RxD (io), 6 NIC, 7 P3.1/TxD (io), 8 P3.2/~{INT}0 (io), 9 P3.3/~{INT}1 (io), 10 P3.4/T0 (io), 11 P3.5/T1 (io), 12 P3.6/~{WR} (io), 13 P3.7/~{RD} (io), 14 XTAL2 (out), 15 XTAL1 (in), 16 VSS (power), 17 NIC, 18 P2.0/A8 (io), 19 P2.1/A9 (io), 20 P2.2/A10 (io), 21 P2.3/A11 (io), 22 P2.4/A12 (io), 23 P2.5/A13 (io), 24 P2.6/A14 (io), 25 P2.7/A15 (io), 26 ~{PSEN} (out), 27 ALE/~{PROG} (io), 28 NIC, 29 ~{EA}/VPP (in), 30 P0.7/AD7 (io), 31 P0.6/AD6 (io), 32 P0.5/AD5 (io), 33 P0.4/AD4 (io), 34 P0.3/AD3 (io), 35 P0.2/AD2 (io), 36 P0.1/AD1 (io), 37 P0.0/AD0 (io), 38 VCC (power), 39 NIC, 40 P1.0/T2 (io), 41 P1.1/T2EX (io), 42 P1.2/ECI (io), 43 P1.3/CEX0 (io), 44 P1.4/CEX1 (io)

## P87C51FB-IN
designator U?
80C51 8-Bit Microcontroller Family: 256 B RAM, 16 kB OTP, 5V, Low Power, High Speed
footprint SOT129-1 (DIP, Plastic; 40 Leads; Row Spacing 15.24 mm; Pitch 2.54 mm)
pins: 1 P1.0/T2 (io), 2 P1.1/T2EX (io), 3 P1.2/ECI (io), 4 P1.3/CEX0 (io), 5 P1.4/CEX1 (io), 6 P1.5/CEX2 (io), 7 P1.6/CEX3 (io), 8 P1.7/CEX4 (io), 9 RST (in), 10 P3.0/RxD (io), 11 P3.1/TxD (io), 12 P3.2/~{INT}0 (io), 13 P3.3/~{INT}1 (io), 14 P3.4/T0 (io), 15 P3.5/T1 (io), 16 P3.6/~{WR} (io), 17 P3.7/~{RD} (io), 18 XTAL2 (out), 19 XTAL1 (in), 20 VSS (power), 21 P2.0/A8 (io), 22 P2.1/A9 (io), 23 P2.2/A10 (io), 24 P2.3/A11 (io), 25 P2.4/A12 (io), 26 P2.5/A13 (io), 27 P2.6/A14 (io), 28 P2.7/A15 (io), 29 ~{PSEN} (out), 30 ALE/~{PROG} (io), 31 ~{EA}/VPP (in), 32 P0.7/AD7 (io), 33 P0.6/AD6 (io), 34 P0.5/AD5 (io), 35 P0.4/AD4 (io), 36 P0.3/AD3 (io), 37 P0.2/AD2 (io), 38 P0.1/AD1 (io), 39 P0.0/AD0 (io), 40 VCC (power)

## P87C51FB-JA
designator U?
80C51 8-Bit Microcontroller Family: 256 B RAM, 16 kB OTP, 5V, Low Power, High Speed
footprint SOT187-2_N (Leaded Chip Carrier, 44-Leads, Body 16.6x16.6mm, Pitch 1.27mm, IPC Medium Density)
footprint SOT187-2_L (Leaded Chip Carrier, 44-Leads, Body 16.6x16.6mm, Pitch 1.27mm, IPC High Density)
footprint SOT187-2_M (Leaded Chip Carrier, 44-Leads, Body 16.6x16.6mm, Pitch 1.27mm, IPC Low Density)
pins: 1 NIC, 2 P1.0/T2 (io), 3 P1.1/T2EX (io), 4 P1.2/ECI (io), 5 P1.3/CEX0 (io), 6 P1.4/CEX1 (io), 7 P1.5/CEX2 (io), 8 P1.6/CEX3 (io), 9 P1.7/CEX4 (io), 10 RST (in), 11 P3.0/RxD (io), 12 NIC, 13 P3.1/TxD (io), 14 P3.2/~{INT}0 (io), 15 P3.3/~{INT}1 (io), 16 P3.4/T0 (io), 17 P3.5/T1 (io), 18 P3.6/~{WR} (io), 19 P3.7/~{RD} (io), 20 XTAL2 (out), 21 XTAL1 (in), 22 VSS (power), 23 NIC, 24 P2.0/A8 (io), 25 P2.1/A9 (io), 26 P2.2/A10 (io), 27 P2.3/A11 (io), 28 P2.4/A12 (io), 29 P2.5/A13 (io), 30 P2.6/A14 (io), 31 P2.7/A15 (io), 32 ~{PSEN} (out), 33 ALE/~{PROG} (io), 34 NIC, 35 ~{EA}/VPP (in), 36 P0.7/AD7 (io), 37 P0.6/AD6 (io), 38 P0.5/AD5 (io), 39 P0.4/AD4 (io), 40 P0.3/AD3 (io), 41 P0.2/AD2 (io), 42 P0.1/AD1 (io), 43 P0.0/AD0 (io), 44 VCC (power)

## P87C51FB-JB
designator U?
80C51 8-Bit Microcontroller Family: 256 B RAM, 16 kB OTP, 5V, Low Power, High Speed
footprint SOT307-2_N (QFP, 44-Leads, Body 10x10mm, Pitch 0.8mm, IPC Medium Density)
footprint SOT307-2_L (QFP, 44-Leads, Body 10x10mm, Pitch 0.8mm, IPC High Density)
footprint SOT307-2_M (QFP, 44-Leads, Body 10x10mm, Pitch 0.8mm, IPC Low Density)
pins: 1 P1.5/CEX2 (io), 2 P1.6/CEX3 (io), 3 P1.7/CEX4 (io), 4 RST (in), 5 P3.0/RxD (io), 6 NIC, 7 P3.1/TxD (io), 8 P3.2/~{INT}0 (io), 9 P3.3/~{INT}1 (io), 10 P3.4/T0 (io), 11 P3.5/T1 (io), 12 P3.6/~{WR} (io), 13 P3.7/~{RD} (io), 14 XTAL2 (out), 15 XTAL1 (in), 16 VSS (power), 17 NIC, 18 P2.0/A8 (io), 19 P2.1/A9 (io), 20 P2.2/A10 (io), 21 P2.3/A11 (io), 22 P2.4/A12 (io), 23 P2.5/A13 (io), 24 P2.6/A14 (io), 25 P2.7/A15 (io), 26 ~{PSEN} (out), 27 ALE/~{PROG} (io), 28 NIC, 29 ~{EA}/VPP (in), 30 P0.7/AD7 (io), 31 P0.6/AD6 (io), 32 P0.5/AD5 (io), 33 P0.4/AD4 (io), 34 P0.3/AD3 (io), 35 P0.2/AD2 (io), 36 P0.1/AD1 (io), 37 P0.0/AD0 (io), 38 VCC (power), 39 NIC, 40 P1.0/T2 (io), 41 P1.1/T2EX (io), 42 P1.2/ECI (io), 43 P1.3/CEX0 (io), 44 P1.4/CEX1 (io)

## P87C51FB-JN
designator U?
80C51 8-Bit Microcontroller Family: 256 B RAM, 16 kB OTP, 5V, Low Power, High Speed
footprint SOT129-1 (DIP, Plastic; 40 Leads; Row Spacing 15.24 mm; Pitch 2.54 mm)
pins: 1 P1.0/T2 (io), 2 P1.1/T2EX (io), 3 P1.2/ECI (io), 4 P1.3/CEX0 (io), 5 P1.4/CEX1 (io), 6 P1.5/CEX2 (io), 7 P1.6/CEX3 (io), 8 P1.7/CEX4 (io), 9 RST (in), 10 P3.0/RxD (io), 11 P3.1/TxD (io), 12 P3.2/~{INT}0 (io), 13 P3.3/~{INT}1 (io), 14 P3.4/T0 (io), 15 P3.5/T1 (io), 16 P3.6/~{WR} (io), 17 P3.7/~{RD} (io), 18 XTAL2 (out), 19 XTAL1 (in), 20 VSS (power), 21 P2.0/A8 (io), 22 P2.1/A9 (io), 23 P2.2/A10 (io), 24 P2.3/A11 (io), 25 P2.4/A12 (io), 26 P2.5/A13 (io), 27 P2.6/A14 (io), 28 P2.7/A15 (io), 29 ~{PSEN} (out), 30 ALE/~{PROG} (io), 31 ~{EA}/VPP (in), 32 P0.7/AD7 (io), 33 P0.6/AD6 (io), 34 P0.5/AD5 (io), 35 P0.4/AD4 (io), 36 P0.3/AD3 (io), 37 P0.2/AD2 (io), 38 P0.1/AD1 (io), 39 P0.0/AD0 (io), 40 VCC (power)

## P87C51FC-4A
designator U?
80C51 8-Bit Microcontroller Family: 256 B RAM, 32 kB OTP, 2.7V-5.5V, Low Power, High Speed
footprint SOT187-2_N (Leaded Chip Carrier, 44-Leads, Body 16.6x16.6mm, Pitch 1.27mm, IPC Medium Density)
footprint SOT187-2_L (Leaded Chip Carrier, 44-Leads, Body 16.6x16.6mm, Pitch 1.27mm, IPC High Density)
footprint SOT187-2_M (Leaded Chip Carrier, 44-Leads, Body 16.6x16.6mm, Pitch 1.27mm, IPC Low Density)
pins: 1 NIC, 2 P1.0/T2 (io), 3 P1.1/T2EX (io), 4 P1.2/ECI (io), 5 P1.3/CEX0 (io), 6 P1.4/CEX1 (io), 7 P1.5/CEX2 (io), 8 P1.6/CEX3 (io), 9 P1.7/CEX4 (io), 10 RST (in), 11 P3.0/RxD (io), 12 NIC, 13 P3.1/TxD (io), 14 P3.2/~{INT}0 (io), 15 P3.3/~{INT}1 (io), 16 P3.4/T0 (io), 17 P3.5/T1 (io), 18 P3.6/~{WR} (io), 19 P3.7/~{RD} (io), 20 XTAL2 (out), 21 XTAL1 (in), 22 VSS (power), 23 NIC, 24 P2.0/A8 (io), 25 P2.1/A9 (io), 26 P2.2/A10 (io), 27 P2.3/A11 (io), 28 P2.4/A12 (io), 29 P2.5/A13 (io), 30 P2.6/A14 (io), 31 P2.7/A15 (io), 32 ~{PSEN} (out), 33 ALE/~{PROG} (io), 34 NIC, 35 ~{EA}/VPP (in), 36 P0.7/AD7 (io), 37 P0.6/AD6 (io), 38 P0.5/AD5 (io), 39 P0.4/AD4 (io), 40 P0.3/AD3 (io), 41 P0.2/AD2 (io), 42 P0.1/AD1 (io), 43 P0.0/AD0 (io), 44 VCC (power)

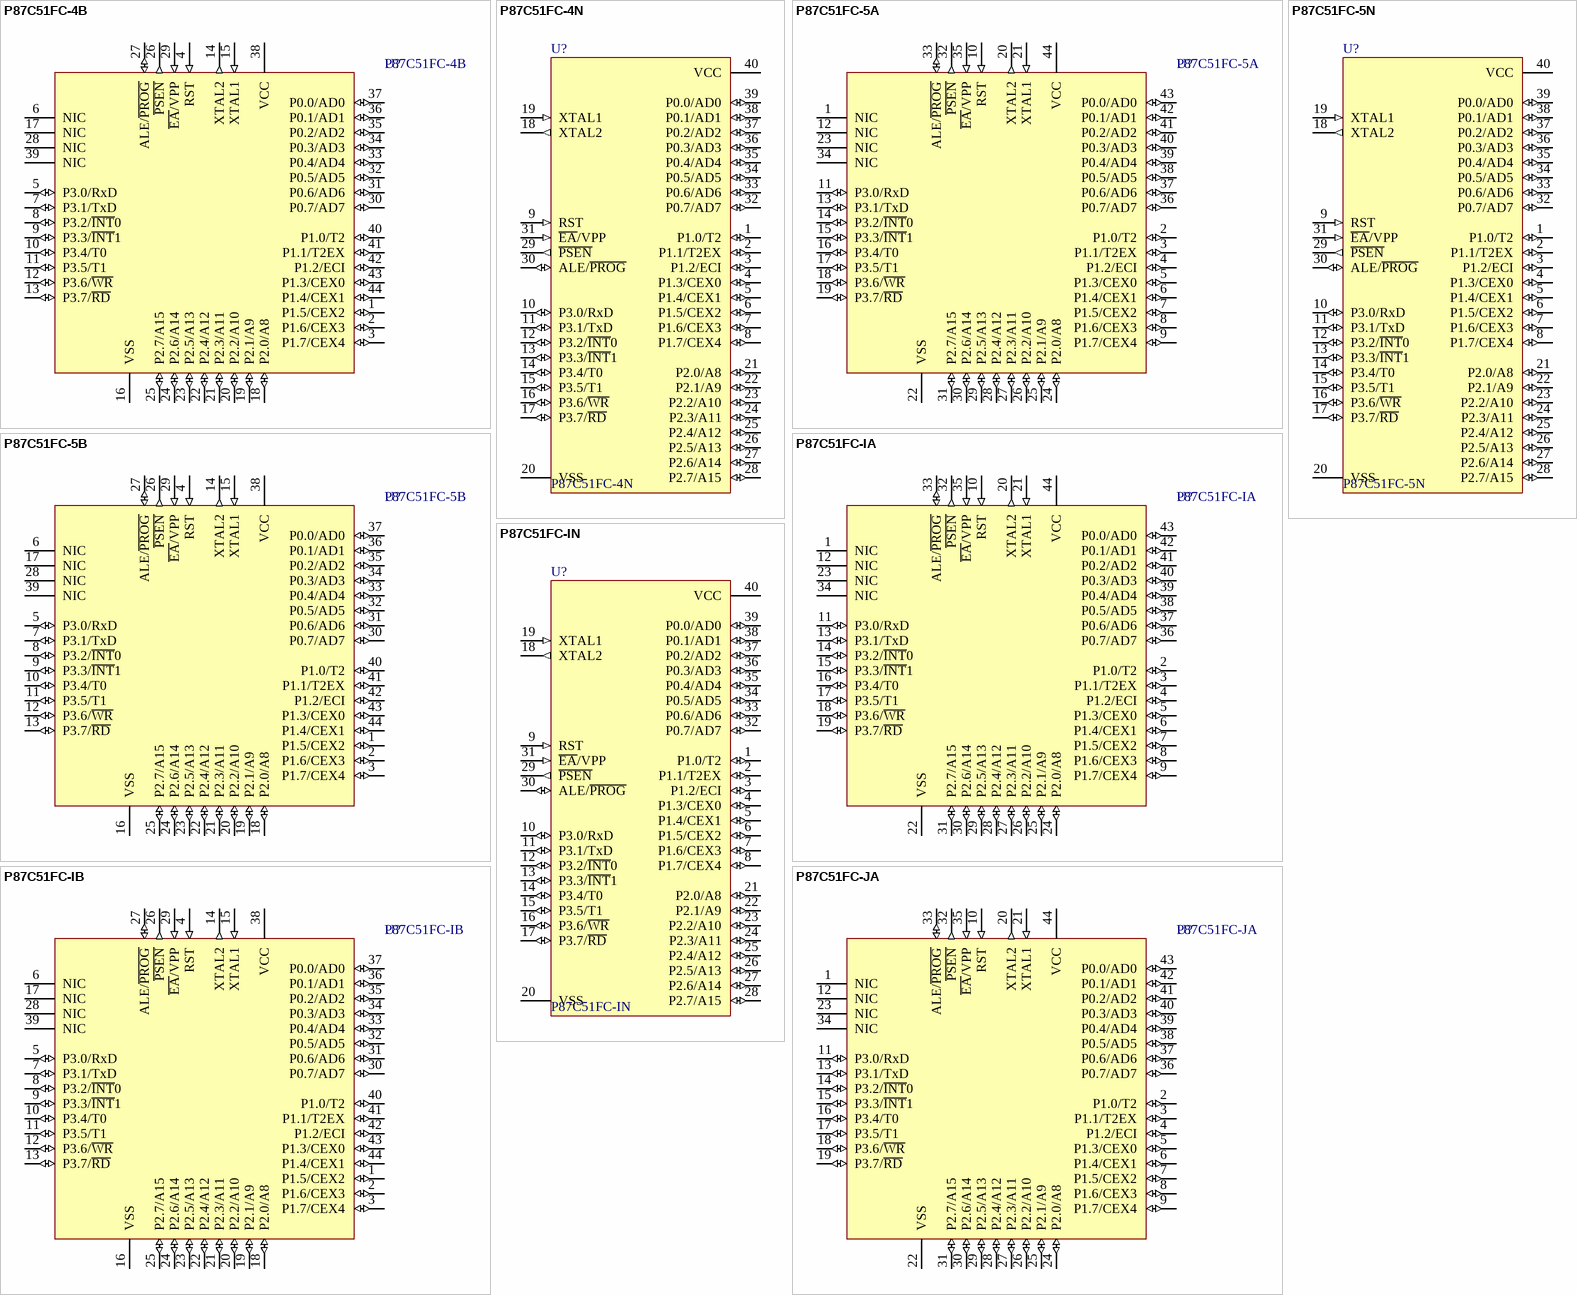
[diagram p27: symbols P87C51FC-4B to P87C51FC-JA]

## P87C51FC-4B
designator U?
80C51 8-Bit Microcontroller Family: 256 B RAM, 32 kB OTP, 2.7V-5.5V, Low Power, High Speed
footprint SOT307-2_N (QFP, 44-Leads, Body 10x10mm, Pitch 0.8mm, IPC Medium Density)
footprint SOT307-2_L (QFP, 44-Leads, Body 10x10mm, Pitch 0.8mm, IPC High Density)
footprint SOT307-2_M (QFP, 44-Leads, Body 10x10mm, Pitch 0.8mm, IPC Low Density)
pins: 1 P1.5/CEX2 (io), 2 P1.6/CEX3 (io), 3 P1.7/CEX4 (io), 4 RST (in), 5 P3.0/RxD (io), 6 NIC, 7 P3.1/TxD (io), 8 P3.2/~{INT}0 (io), 9 P3.3/~{INT}1 (io), 10 P3.4/T0 (io), 11 P3.5/T1 (io), 12 P3.6/~{WR} (io), 13 P3.7/~{RD} (io), 14 XTAL2 (out), 15 XTAL1 (in), 16 VSS (power), 17 NIC, 18 P2.0/A8 (io), 19 P2.1/A9 (io), 20 P2.2/A10 (io), 21 P2.3/A11 (io), 22 P2.4/A12 (io), 23 P2.5/A13 (io), 24 P2.6/A14 (io), 25 P2.7/A15 (io), 26 ~{PSEN} (out), 27 ALE/~{PROG} (io), 28 NIC, 29 ~{EA}/VPP (in), 30 P0.7/AD7 (io), 31 P0.6/AD6 (io), 32 P0.5/AD5 (io), 33 P0.4/AD4 (io), 34 P0.3/AD3 (io), 35 P0.2/AD2 (io), 36 P0.1/AD1 (io), 37 P0.0/AD0 (io), 38 VCC (power), 39 NIC, 40 P1.0/T2 (io), 41 P1.1/T2EX (io), 42 P1.2/ECI (io), 43 P1.3/CEX0 (io), 44 P1.4/CEX1 (io)

## P87C51FC-4N
designator U?
80C51 8-Bit Microcontroller Family: 256 B RAM, 32 kB OTP, 2.7V-5.5V, Low Power, High Speed
footprint SOT129-1 (DIP, Plastic; 40 Leads; Row Spacing 15.24 mm; Pitch 2.54 mm)
pins: 1 P1.0/T2 (io), 2 P1.1/T2EX (io), 3 P1.2/ECI (io), 4 P1.3/CEX0 (io), 5 P1.4/CEX1 (io), 6 P1.5/CEX2 (io), 7 P1.6/CEX3 (io), 8 P1.7/CEX4 (io), 9 RST (in), 10 P3.0/RxD (io), 11 P3.1/TxD (io), 12 P3.2/~{INT}0 (io), 13 P3.3/~{INT}1 (io), 14 P3.4/T0 (io), 15 P3.5/T1 (io), 16 P3.6/~{WR} (io), 17 P3.7/~{RD} (io), 18 XTAL2 (out), 19 XTAL1 (in), 20 VSS (power), 21 P2.0/A8 (io), 22 P2.1/A9 (io), 23 P2.2/A10 (io), 24 P2.3/A11 (io), 25 P2.4/A12 (io), 26 P2.5/A13 (io), 27 P2.6/A14 (io), 28 P2.7/A15 (io), 29 ~{PSEN} (out), 30 ALE/~{PROG} (io), 31 ~{EA}/VPP (in), 32 P0.7/AD7 (io), 33 P0.6/AD6 (io), 34 P0.5/AD5 (io), 35 P0.4/AD4 (io), 36 P0.3/AD3 (io), 37 P0.2/AD2 (io), 38 P0.1/AD1 (io), 39 P0.0/AD0 (io), 40 VCC (power)

## P87C51FC-5A
designator U?
80C51 8-Bit Microcontroller Family: 256 B RAM, 32 kB OTP, 2.7V-5.5V, Low Power, High Speed
footprint SOT187-2_N (Leaded Chip Carrier, 44-Leads, Body 16.6x16.6mm, Pitch 1.27mm, IPC Medium Density)
footprint SOT187-2_L (Leaded Chip Carrier, 44-Leads, Body 16.6x16.6mm, Pitch 1.27mm, IPC High Density)
footprint SOT187-2_M (Leaded Chip Carrier, 44-Leads, Body 16.6x16.6mm, Pitch 1.27mm, IPC Low Density)
pins: 1 NIC, 2 P1.0/T2 (io), 3 P1.1/T2EX (io), 4 P1.2/ECI (io), 5 P1.3/CEX0 (io), 6 P1.4/CEX1 (io), 7 P1.5/CEX2 (io), 8 P1.6/CEX3 (io), 9 P1.7/CEX4 (io), 10 RST (in), 11 P3.0/RxD (io), 12 NIC, 13 P3.1/TxD (io), 14 P3.2/~{INT}0 (io), 15 P3.3/~{INT}1 (io), 16 P3.4/T0 (io), 17 P3.5/T1 (io), 18 P3.6/~{WR} (io), 19 P3.7/~{RD} (io), 20 XTAL2 (out), 21 XTAL1 (in), 22 VSS (power), 23 NIC, 24 P2.0/A8 (io), 25 P2.1/A9 (io), 26 P2.2/A10 (io), 27 P2.3/A11 (io), 28 P2.4/A12 (io), 29 P2.5/A13 (io), 30 P2.6/A14 (io), 31 P2.7/A15 (io), 32 ~{PSEN} (out), 33 ALE/~{PROG} (io), 34 NIC, 35 ~{EA}/VPP (in), 36 P0.7/AD7 (io), 37 P0.6/AD6 (io), 38 P0.5/AD5 (io), 39 P0.4/AD4 (io), 40 P0.3/AD3 (io), 41 P0.2/AD2 (io), 42 P0.1/AD1 (io), 43 P0.0/AD0 (io), 44 VCC (power)

## P87C51FC-5B
designator U?
80C51 8-Bit Microcontroller Family: 256 B RAM, 32 kB OTP, 2.7V-5.5V, Low Power, High Speed
footprint SOT307-2_N (QFP, 44-Leads, Body 10x10mm, Pitch 0.8mm, IPC Medium Density)
footprint SOT307-2_L (QFP, 44-Leads, Body 10x10mm, Pitch 0.8mm, IPC High Density)
footprint SOT307-2_M (QFP, 44-Leads, Body 10x10mm, Pitch 0.8mm, IPC Low Density)
pins: 1 P1.5/CEX2 (io), 2 P1.6/CEX3 (io), 3 P1.7/CEX4 (io), 4 RST (in), 5 P3.0/RxD (io), 6 NIC, 7 P3.1/TxD (io), 8 P3.2/~{INT}0 (io), 9 P3.3/~{INT}1 (io), 10 P3.4/T0 (io), 11 P3.5/T1 (io), 12 P3.6/~{WR} (io), 13 P3.7/~{RD} (io), 14 XTAL2 (out), 15 XTAL1 (in), 16 VSS (power), 17 NIC, 18 P2.0/A8 (io), 19 P2.1/A9 (io), 20 P2.2/A10 (io), 21 P2.3/A11 (io), 22 P2.4/A12 (io), 23 P2.5/A13 (io), 24 P2.6/A14 (io), 25 P2.7/A15 (io), 26 ~{PSEN} (out), 27 ALE/~{PROG} (io), 28 NIC, 29 ~{EA}/VPP (in), 30 P0.7/AD7 (io), 31 P0.6/AD6 (io), 32 P0.5/AD5 (io), 33 P0.4/AD4 (io), 34 P0.3/AD3 (io), 35 P0.2/AD2 (io), 36 P0.1/AD1 (io), 37 P0.0/AD0 (io), 38 VCC (power), 39 NIC, 40 P1.0/T2 (io), 41 P1.1/T2EX (io), 42 P1.2/ECI (io), 43 P1.3/CEX0 (io), 44 P1.4/CEX1 (io)

## P87C51FC-5N
designator U?
80C51 8-Bit Microcontroller Family: 256 B RAM, 32 kB OTP, 2.7V-5.5V, Low Power, High Speed
footprint SOT129-1 (DIP, Plastic; 40 Leads; Row Spacing 15.24 mm; Pitch 2.54 mm)
pins: 1 P1.0/T2 (io), 2 P1.1/T2EX (io), 3 P1.2/ECI (io), 4 P1.3/CEX0 (io), 5 P1.4/CEX1 (io), 6 P1.5/CEX2 (io), 7 P1.6/CEX3 (io), 8 P1.7/CEX4 (io), 9 RST (in), 10 P3.0/RxD (io), 11 P3.1/TxD (io), 12 P3.2/~{INT}0 (io), 13 P3.3/~{INT}1 (io), 14 P3.4/T0 (io), 15 P3.5/T1 (io), 16 P3.6/~{WR} (io), 17 P3.7/~{RD} (io), 18 XTAL2 (out), 19 XTAL1 (in), 20 VSS (power), 21 P2.0/A8 (io), 22 P2.1/A9 (io), 23 P2.2/A10 (io), 24 P2.3/A11 (io), 25 P2.4/A12 (io), 26 P2.5/A13 (io), 27 P2.6/A14 (io), 28 P2.7/A15 (io), 29 ~{PSEN} (out), 30 ALE/~{PROG} (io), 31 ~{EA}/VPP (in), 32 P0.7/AD7 (io), 33 P0.6/AD6 (io), 34 P0.5/AD5 (io), 35 P0.4/AD4 (io), 36 P0.3/AD3 (io), 37 P0.2/AD2 (io), 38 P0.1/AD1 (io), 39 P0.0/AD0 (io), 40 VCC (power)

## P87C51FC-IA
designator U?
80C51 8-Bit Microcontroller Family: 256 B RAM, 32 kB OTP, 5V, Low Power, High Speed
footprint SOT187-2_N (Leaded Chip Carrier, 44-Leads, Body 16.6x16.6mm, Pitch 1.27mm, IPC Medium Density)
footprint SOT187-2_L (Leaded Chip Carrier, 44-Leads, Body 16.6x16.6mm, Pitch 1.27mm, IPC High Density)
footprint SOT187-2_M (Leaded Chip Carrier, 44-Leads, Body 16.6x16.6mm, Pitch 1.27mm, IPC Low Density)
pins: 1 NIC, 2 P1.0/T2 (io), 3 P1.1/T2EX (io), 4 P1.2/ECI (io), 5 P1.3/CEX0 (io), 6 P1.4/CEX1 (io), 7 P1.5/CEX2 (io), 8 P1.6/CEX3 (io), 9 P1.7/CEX4 (io), 10 RST (in), 11 P3.0/RxD (io), 12 NIC, 13 P3.1/TxD (io), 14 P3.2/~{INT}0 (io), 15 P3.3/~{INT}1 (io), 16 P3.4/T0 (io), 17 P3.5/T1 (io), 18 P3.6/~{WR} (io), 19 P3.7/~{RD} (io), 20 XTAL2 (out), 21 XTAL1 (in), 22 VSS (power), 23 NIC, 24 P2.0/A8 (io), 25 P2.1/A9 (io), 26 P2.2/A10 (io), 27 P2.3/A11 (io), 28 P2.4/A12 (io), 29 P2.5/A13 (io), 30 P2.6/A14 (io), 31 P2.7/A15 (io), 32 ~{PSEN} (out), 33 ALE/~{PROG} (io), 34 NIC, 35 ~{EA}/VPP (in), 36 P0.7/AD7 (io), 37 P0.6/AD6 (io), 38 P0.5/AD5 (io), 39 P0.4/AD4 (io), 40 P0.3/AD3 (io), 41 P0.2/AD2 (io), 42 P0.1/AD1 (io), 43 P0.0/AD0 (io), 44 VCC (power)

## P87C51FC-IB
designator U?
80C51 8-Bit Microcontroller Family: 256 B RAM, 32 kB OTP, 5V, Low Power, High Speed
footprint SOT307-2_N (QFP, 44-Leads, Body 10x10mm, Pitch 0.8mm, IPC Medium Density)
footprint SOT307-2_L (QFP, 44-Leads, Body 10x10mm, Pitch 0.8mm, IPC High Density)
footprint SOT307-2_M (QFP, 44-Leads, Body 10x10mm, Pitch 0.8mm, IPC Low Density)
pins: 1 P1.5/CEX2 (io), 2 P1.6/CEX3 (io), 3 P1.7/CEX4 (io), 4 RST (in), 5 P3.0/RxD (io), 6 NIC, 7 P3.1/TxD (io), 8 P3.2/~{INT}0 (io), 9 P3.3/~{INT}1 (io), 10 P3.4/T0 (io), 11 P3.5/T1 (io), 12 P3.6/~{WR} (io), 13 P3.7/~{RD} (io), 14 XTAL2 (out), 15 XTAL1 (in), 16 VSS (power), 17 NIC, 18 P2.0/A8 (io), 19 P2.1/A9 (io), 20 P2.2/A10 (io), 21 P2.3/A11 (io), 22 P2.4/A12 (io), 23 P2.5/A13 (io), 24 P2.6/A14 (io), 25 P2.7/A15 (io), 26 ~{PSEN} (out), 27 ALE/~{PROG} (io), 28 NIC, 29 ~{EA}/VPP (in), 30 P0.7/AD7 (io), 31 P0.6/AD6 (io), 32 P0.5/AD5 (io), 33 P0.4/AD4 (io), 34 P0.3/AD3 (io), 35 P0.2/AD2 (io), 36 P0.1/AD1 (io), 37 P0.0/AD0 (io), 38 VCC (power), 39 NIC, 40 P1.0/T2 (io), 41 P1.1/T2EX (io), 42 P1.2/ECI (io), 43 P1.3/CEX0 (io), 44 P1.4/CEX1 (io)

## P87C51FC-IN
designator U?
80C51 8-Bit Microcontroller Family: 256 B RAM, 32 kB OTP, 5V, Low Power, High Speed
footprint SOT129-1 (DIP, Plastic; 40 Leads; Row Spacing 15.24 mm; Pitch 2.54 mm)
pins: 1 P1.0/T2 (io), 2 P1.1/T2EX (io), 3 P1.2/ECI (io), 4 P1.3/CEX0 (io), 5 P1.4/CEX1 (io), 6 P1.5/CEX2 (io), 7 P1.6/CEX3 (io), 8 P1.7/CEX4 (io), 9 RST (in), 10 P3.0/RxD (io), 11 P3.1/TxD (io), 12 P3.2/~{INT}0 (io), 13 P3.3/~{INT}1 (io), 14 P3.4/T0 (io), 15 P3.5/T1 (io), 16 P3.6/~{WR} (io), 17 P3.7/~{RD} (io), 18 XTAL2 (out), 19 XTAL1 (in), 20 VSS (power), 21 P2.0/A8 (io), 22 P2.1/A9 (io), 23 P2.2/A10 (io), 24 P2.3/A11 (io), 25 P2.4/A12 (io), 26 P2.5/A13 (io), 27 P2.6/A14 (io), 28 P2.7/A15 (io), 29 ~{PSEN} (out), 30 ALE/~{PROG} (io), 31 ~{EA}/VPP (in), 32 P0.7/AD7 (io), 33 P0.6/AD6 (io), 34 P0.5/AD5 (io), 35 P0.4/AD4 (io), 36 P0.3/AD3 (io), 37 P0.2/AD2 (io), 38 P0.1/AD1 (io), 39 P0.0/AD0 (io), 40 VCC (power)

## P87C51FC-JA
designator U?
80C51 8-Bit Microcontroller Family: 256 B RAM, 32 kB OTP, 5V, Low Power, High Speed
footprint SOT187-2_N (Leaded Chip Carrier, 44-Leads, Body 16.6x16.6mm, Pitch 1.27mm, IPC Medium Density)
footprint SOT187-2_L (Leaded Chip Carrier, 44-Leads, Body 16.6x16.6mm, Pitch 1.27mm, IPC High Density)
footprint SOT187-2_M (Leaded Chip Carrier, 44-Leads, Body 16.6x16.6mm, Pitch 1.27mm, IPC Low Density)
pins: 1 NIC, 2 P1.0/T2 (io), 3 P1.1/T2EX (io), 4 P1.2/ECI (io), 5 P1.3/CEX0 (io), 6 P1.4/CEX1 (io), 7 P1.5/CEX2 (io), 8 P1.6/CEX3 (io), 9 P1.7/CEX4 (io), 10 RST (in), 11 P3.0/RxD (io), 12 NIC, 13 P3.1/TxD (io), 14 P3.2/~{INT}0 (io), 15 P3.3/~{INT}1 (io), 16 P3.4/T0 (io), 17 P3.5/T1 (io), 18 P3.6/~{WR} (io), 19 P3.7/~{RD} (io), 20 XTAL2 (out), 21 XTAL1 (in), 22 VSS (power), 23 NIC, 24 P2.0/A8 (io), 25 P2.1/A9 (io), 26 P2.2/A10 (io), 27 P2.3/A11 (io), 28 P2.4/A12 (io), 29 P2.5/A13 (io), 30 P2.6/A14 (io), 31 P2.7/A15 (io), 32 ~{PSEN} (out), 33 ALE/~{PROG} (io), 34 NIC, 35 ~{EA}/VPP (in), 36 P0.7/AD7 (io), 37 P0.6/AD6 (io), 38 P0.5/AD5 (io), 39 P0.4/AD4 (io), 40 P0.3/AD3 (io), 41 P0.2/AD2 (io), 42 P0.1/AD1 (io), 43 P0.0/AD0 (io), 44 VCC (power)

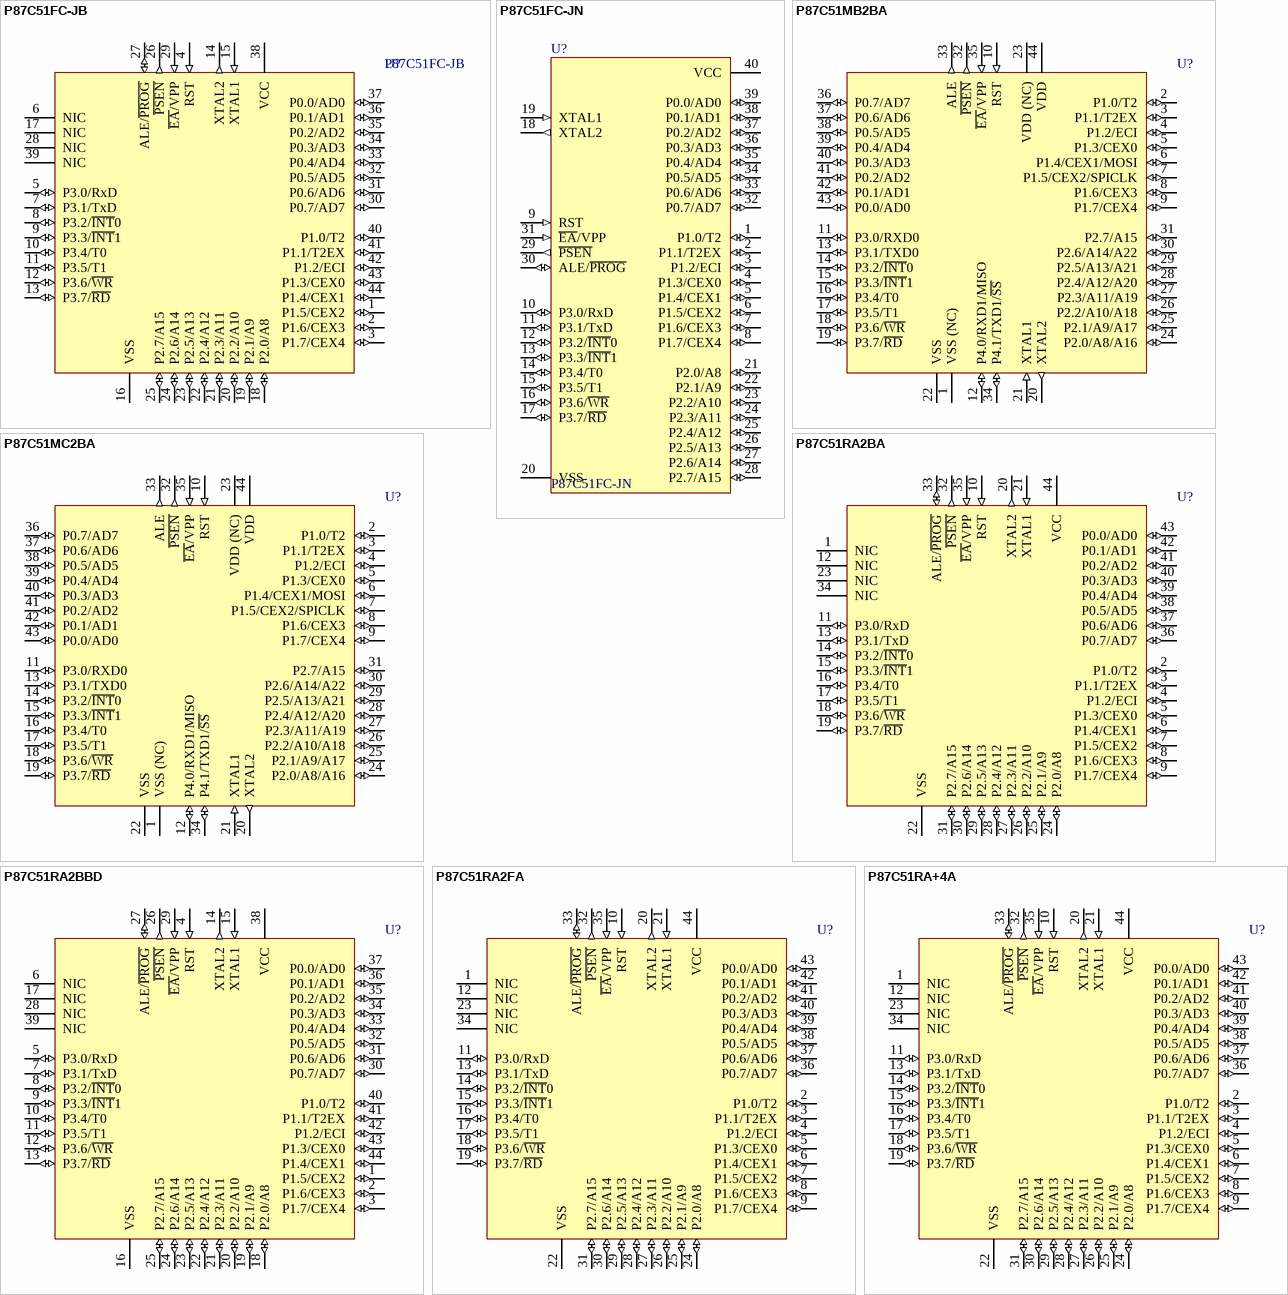
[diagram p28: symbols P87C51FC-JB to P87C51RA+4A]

## P87C51FC-JB
designator U?
80C51 8-Bit Microcontroller Family: 256 B RAM, 32 kB OTP, 5V, Low Power, High Speed
footprint SOT307-2_N (QFP, 44-Leads, Body 10x10mm, Pitch 0.8mm, IPC Medium Density)
footprint SOT307-2_L (QFP, 44-Leads, Body 10x10mm, Pitch 0.8mm, IPC High Density)
footprint SOT307-2_M (QFP, 44-Leads, Body 10x10mm, Pitch 0.8mm, IPC Low Density)
pins: 1 P1.5/CEX2 (io), 2 P1.6/CEX3 (io), 3 P1.7/CEX4 (io), 4 RST (in), 5 P3.0/RxD (io), 6 NIC, 7 P3.1/TxD (io), 8 P3.2/~{INT}0 (io), 9 P3.3/~{INT}1 (io), 10 P3.4/T0 (io), 11 P3.5/T1 (io), 12 P3.6/~{WR} (io), 13 P3.7/~{RD} (io), 14 XTAL2 (out), 15 XTAL1 (in), 16 VSS (power), 17 NIC, 18 P2.0/A8 (io), 19 P2.1/A9 (io), 20 P2.2/A10 (io), 21 P2.3/A11 (io), 22 P2.4/A12 (io), 23 P2.5/A13 (io), 24 P2.6/A14 (io), 25 P2.7/A15 (io), 26 ~{PSEN} (out), 27 ALE/~{PROG} (io), 28 NIC, 29 ~{EA}/VPP (in), 30 P0.7/AD7 (io), 31 P0.6/AD6 (io), 32 P0.5/AD5 (io), 33 P0.4/AD4 (io), 34 P0.3/AD3 (io), 35 P0.2/AD2 (io), 36 P0.1/AD1 (io), 37 P0.0/AD0 (io), 38 VCC (power), 39 NIC, 40 P1.0/T2 (io), 41 P1.1/T2EX (io), 42 P1.2/ECI (io), 43 P1.3/CEX0 (io), 44 P1.4/CEX1 (io)

## P87C51FC-JN
designator U?
80C51 8-Bit Microcontroller Family: 256 B RAM, 32 kB OTP, 5V, Low Power, High Speed
footprint SOT129-1 (DIP, Plastic; 40 Leads; Row Spacing 15.24 mm; Pitch 2.54 mm)
pins: 1 P1.0/T2 (io), 2 P1.1/T2EX (io), 3 P1.2/ECI (io), 4 P1.3/CEX0 (io), 5 P1.4/CEX1 (io), 6 P1.5/CEX2 (io), 7 P1.6/CEX3 (io), 8 P1.7/CEX4 (io), 9 RST (in), 10 P3.0/RxD (io), 11 P3.1/TxD (io), 12 P3.2/~{INT}0 (io), 13 P3.3/~{INT}1 (io), 14 P3.4/T0 (io), 15 P3.5/T1 (io), 16 P3.6/~{WR} (io), 17 P3.7/~{RD} (io), 18 XTAL2 (out), 19 XTAL1 (in), 20 VSS (power), 21 P2.0/A8 (io), 22 P2.1/A9 (io), 23 P2.2/A10 (io), 24 P2.3/A11 (io), 25 P2.4/A12 (io), 26 P2.5/A13 (io), 27 P2.6/A14 (io), 28 P2.7/A15 (io), 29 ~{PSEN} (out), 30 ALE/~{PROG} (io), 31 ~{EA}/VPP (in), 32 P0.7/AD7 (io), 33 P0.6/AD6 (io), 34 P0.5/AD5 (io), 35 P0.4/AD4 (io), 36 P0.3/AD3 (io), 37 P0.2/AD2 (io), 38 P0.1/AD1 (io), 39 P0.0/AD0 (io), 40 VCC (power)

## P87C51MB2BA
designator U?
80C51 8-Bit Microcontroller Family with Extended Memory: 64 kB OTP with 2 kB RAM; Note: Pins 1 & 23 are not connected on some derivatives, but internally connected to VSS and VDD respectively on the P87C51Mx2.; Note: Pins 12 & 34 not connected pins on some derivatives.
footprint SOT187-2_N (Leaded Chip Carrier, 44-Leads, Body 16.6x16.6mm, Pitch 1.27mm, IPC Medium Density)
footprint SOT187-2_L (Leaded Chip Carrier, 44-Leads, Body 16.6x16.6mm, Pitch 1.27mm, IPC High Density)
footprint SOT187-2_M (Leaded Chip Carrier, 44-Leads, Body 16.6x16.6mm, Pitch 1.27mm, IPC Low Density)
pins: 1 VSS (NC) (power), 2 P1.0/T2 (io), 3 P1.1/T2EX (io), 4 P1.2/ECI (io), 5 P1.3/CEX0 (io), 6 P1.4/CEX1/MOSI (io), 7 P1.5/CEX2/SPICLK (io), 8 P1.6/CEX3 (io), 9 P1.7/CEX4 (io), 10 RST (in), 11 P3.0/RXD0 (io), 12 P4.0/RXD1/MISO (io), 13 P3.1/TXD0 (io), 14 P3.2/~{INT}0 (io), 15 P3.3/~{INT}1 (io), 16 P3.4/T0 (io), 17 P3.5/T1 (io), 18 P3.6/~{WR} (io), 19 P3.7/~{RD} (io), 20 XTAL2 (out), 21 XTAL1 (in), 22 VSS (power), 23 VDD (NC) (power), 24 P2.0/A8/A16 (io), 25 P2.1/A9/A17 (io), 26 P2.2/A10/A18 (io), 27 P2.3/A11/A19 (io), 28 P2.4/A12/A20 (io), 29 P2.5/A13/A21 (io), 30 P2.6/A14/A22 (io), 31 P2.7/A15 (io), 32 ~{PSEN} (out), 33 ALE (out), 34 P4.1/TXD1/~{SS} (io), 35 ~{EA}/VPP (in), 36 P0.7/AD7 (io), 37 P0.6/AD6 (io), 38 P0.5/AD5 (io), 39 P0.4/AD4 (io), 40 P0.3/AD3 (io), 41 P0.2/AD2 (io), 42 P0.1/AD1 (io), 43 P0.0/AD0 (io), 44 VDD (power)

## P87C51MC2BA
designator U?
80C51 8-Bit Microcontroller Family with Extended Memory: 96 kB OTP with 3 kB RAM; Note: Pins 1 & 23 are not connected on some derivatives, but internally connected to VSS and VDD respectively on the P87C51Mx2.; Note: Pins 12 & 34 not connected pins on some derivatives.
footprint SOT187-2_N (Leaded Chip Carrier, 44-Leads, Body 16.6x16.6mm, Pitch 1.27mm, IPC Medium Density)
footprint SOT187-2_L (Leaded Chip Carrier, 44-Leads, Body 16.6x16.6mm, Pitch 1.27mm, IPC High Density)
footprint SOT187-2_M (Leaded Chip Carrier, 44-Leads, Body 16.6x16.6mm, Pitch 1.27mm, IPC Low Density)
pins: 1 VSS (NC) (power), 2 P1.0/T2 (io), 3 P1.1/T2EX (io), 4 P1.2/ECI (io), 5 P1.3/CEX0 (io), 6 P1.4/CEX1/MOSI (io), 7 P1.5/CEX2/SPICLK (io), 8 P1.6/CEX3 (io), 9 P1.7/CEX4 (io), 10 RST (in), 11 P3.0/RXD0 (io), 12 P4.0/RXD1/MISO (io), 13 P3.1/TXD0 (io), 14 P3.2/~{INT}0 (io), 15 P3.3/~{INT}1 (io), 16 P3.4/T0 (io), 17 P3.5/T1 (io), 18 P3.6/~{WR} (io), 19 P3.7/~{RD} (io), 20 XTAL2 (out), 21 XTAL1 (in), 22 VSS (power), 23 VDD (NC) (power), 24 P2.0/A8/A16 (io), 25 P2.1/A9/A17 (io), 26 P2.2/A10/A18 (io), 27 P2.3/A11/A19 (io), 28 P2.4/A12/A20 (io), 29 P2.5/A13/A21 (io), 30 P2.6/A14/A22 (io), 31 P2.7/A15 (io), 32 ~{PSEN} (out), 33 ALE (out), 34 P4.1/TXD1/~{SS} (io), 35 ~{EA}/VPP (in), 36 P0.7/AD7 (io), 37 P0.6/AD6 (io), 38 P0.5/AD5 (io), 39 P0.4/AD4 (io), 40 P0.3/AD3 (io), 41 P0.2/AD2 (io), 42 P0.1/AD1 (io), 43 P0.0/AD0 (io), 44 VDD (power)

## P87C51RA2BA
designator U?
80C51 8-Bit Microcontroller Family: 8 kB OTP with 512 B RAM, 2.7 to 5.5 V, Low Power, High Speed
footprint SOT187-2_N (Leaded Chip Carrier, 44-Leads, Body 16.6x16.6mm, Pitch 1.27mm, IPC Medium Density)
footprint SOT187-2_L (Leaded Chip Carrier, 44-Leads, Body 16.6x16.6mm, Pitch 1.27mm, IPC High Density)
footprint SOT187-2_M (Leaded Chip Carrier, 44-Leads, Body 16.6x16.6mm, Pitch 1.27mm, IPC Low Density)
pins: 1 NIC, 2 P1.0/T2 (io), 3 P1.1/T2EX (io), 4 P1.2/ECI (io), 5 P1.3/CEX0 (io), 6 P1.4/CEX1 (io), 7 P1.5/CEX2 (io), 8 P1.6/CEX3 (io), 9 P1.7/CEX4 (io), 10 RST (in), 11 P3.0/RxD (io), 12 NIC, 13 P3.1/TxD (io), 14 P3.2/~{INT}0 (io), 15 P3.3/~{INT}1 (io), 16 P3.4/T0 (io), 17 P3.5/T1 (io), 18 P3.6/~{WR} (io), 19 P3.7/~{RD} (io), 20 XTAL2 (out), 21 XTAL1 (in), 22 VSS (power), 23 NIC, 24 P2.0/A8 (io), 25 P2.1/A9 (io), 26 P2.2/A10 (io), 27 P2.3/A11 (io), 28 P2.4/A12 (io), 29 P2.5/A13 (io), 30 P2.6/A14 (io), 31 P2.7/A15 (io), 32 ~{PSEN} (out), 33 ALE/~{PROG} (io), 34 NIC, 35 ~{EA}/VPP (in), 36 P0.7/AD7 (io), 37 P0.6/AD6 (io), 38 P0.5/AD5 (io), 39 P0.4/AD4 (io), 40 P0.3/AD3 (io), 41 P0.2/AD2 (io), 42 P0.1/AD1 (io), 43 P0.0/AD0 (io), 44 VCC (power)

## P87C51RA2BBD
designator U?
80C51 8-Bit Microcontroller Family: 8 kB OTP with 512 B RAM, 2.7 to 5.5 V, Low Power, High Speed
footprint SOT389-1_N (Thin QFP, 44-Leads, Body 10x10mm, Pitch 0.8mm, IPC Medium Density)
footprint SOT389-1_L (Thin QFP, 44-Leads, Body 10x10mm, Pitch 0.8mm, IPC High Density)
footprint SOT389-1_M (Thin QFP, 44-Leads, Body 10x10mm, Pitch 0.8mm, IPC Low Density)
pins: 1 P1.5/CEX2 (io), 2 P1.6/CEX3 (io), 3 P1.7/CEX4 (io), 4 RST (in), 5 P3.0/RxD (io), 6 NIC, 7 P3.1/TxD (io), 8 P3.2/~{INT}0 (io), 9 P3.3/~{INT}1 (io), 10 P3.4/T0 (io), 11 P3.5/T1 (io), 12 P3.6/~{WR} (io), 13 P3.7/~{RD} (io), 14 XTAL2 (out), 15 XTAL1 (in), 16 VSS (power), 17 NIC, 18 P2.0/A8 (io), 19 P2.1/A9 (io), 20 P2.2/A10 (io), 21 P2.3/A11 (io), 22 P2.4/A12 (io), 23 P2.5/A13 (io), 24 P2.6/A14 (io), 25 P2.7/A15 (io), 26 ~{PSEN} (out), 27 ALE/~{PROG} (io), 28 NIC, 29 ~{EA}/VPP (in), 30 P0.7/AD7 (io), 31 P0.6/AD6 (io), 32 P0.5/AD5 (io), 33 P0.4/AD4 (io), 34 P0.3/AD3 (io), 35 P0.2/AD2 (io), 36 P0.1/AD1 (io), 37 P0.0/AD0 (io), 38 VCC (power), 39 NIC, 40 P1.0/T2 (io), 41 P1.1/T2EX (io), 42 P1.2/ECI (io), 43 P1.3/CEX0 (io), 44 P1.4/CEX1 (io)

## P87C51RA2FA
designator U?
80C51 8-Bit Microcontroller Family: 8 kB OTP with 512 B RAM, 2.7 to 5.5 V, Low Power, High Speed
footprint SOT187-2_N (Leaded Chip Carrier, 44-Leads, Body 16.6x16.6mm, Pitch 1.27mm, IPC Medium Density)
footprint SOT187-2_L (Leaded Chip Carrier, 44-Leads, Body 16.6x16.6mm, Pitch 1.27mm, IPC High Density)
footprint SOT187-2_M (Leaded Chip Carrier, 44-Leads, Body 16.6x16.6mm, Pitch 1.27mm, IPC Low Density)
pins: 1 NIC, 2 P1.0/T2 (io), 3 P1.1/T2EX (io), 4 P1.2/ECI (io), 5 P1.3/CEX0 (io), 6 P1.4/CEX1 (io), 7 P1.5/CEX2 (io), 8 P1.6/CEX3 (io), 9 P1.7/CEX4 (io), 10 RST (in), 11 P3.0/RxD (io), 12 NIC, 13 P3.1/TxD (io), 14 P3.2/~{INT}0 (io), 15 P3.3/~{INT}1 (io), 16 P3.4/T0 (io), 17 P3.5/T1 (io), 18 P3.6/~{WR} (io), 19 P3.7/~{RD} (io), 20 XTAL2 (out), 21 XTAL1 (in), 22 VSS (power), 23 NIC, 24 P2.0/A8 (io), 25 P2.1/A9 (io), 26 P2.2/A10 (io), 27 P2.3/A11 (io), 28 P2.4/A12 (io), 29 P2.5/A13 (io), 30 P2.6/A14 (io), 31 P2.7/A15 (io), 32 ~{PSEN} (out), 33 ALE/~{PROG} (io), 34 NIC, 35 ~{EA}/VPP (in), 36 P0.7/AD7 (io), 37 P0.6/AD6 (io), 38 P0.5/AD5 (io), 39 P0.4/AD4 (io), 40 P0.3/AD3 (io), 41 P0.2/AD2 (io), 42 P0.1/AD1 (io), 43 P0.0/AD0 (io), 44 VCC (power)

## P87C51RA+4A
designator U?
80C51 8-Bit Microcontroller Family: 512 B RAM, 8 kB OTP, 2.7V-5.5V, Low Power, High Speed
footprint SOT187-2_N (Leaded Chip Carrier, 44-Leads, Body 16.6x16.6mm, Pitch 1.27mm, IPC Medium Density)
footprint SOT187-2_L (Leaded Chip Carrier, 44-Leads, Body 16.6x16.6mm, Pitch 1.27mm, IPC High Density)
footprint SOT187-2_M (Leaded Chip Carrier, 44-Leads, Body 16.6x16.6mm, Pitch 1.27mm, IPC Low Density)
pins: 1 NIC, 2 P1.0/T2 (io), 3 P1.1/T2EX (io), 4 P1.2/ECI (io), 5 P1.3/CEX0 (io), 6 P1.4/CEX1 (io), 7 P1.5/CEX2 (io), 8 P1.6/CEX3 (io), 9 P1.7/CEX4 (io), 10 RST (in), 11 P3.0/RxD (io), 12 NIC, 13 P3.1/TxD (io), 14 P3.2/~{INT}0 (io), 15 P3.3/~{INT}1 (io), 16 P3.4/T0 (io), 17 P3.5/T1 (io), 18 P3.6/~{WR} (io), 19 P3.7/~{RD} (io), 20 XTAL2 (out), 21 XTAL1 (in), 22 VSS (power), 23 NIC, 24 P2.0/A8 (io), 25 P2.1/A9 (io), 26 P2.2/A10 (io), 27 P2.3/A11 (io), 28 P2.4/A12 (io), 29 P2.5/A13 (io), 30 P2.6/A14 (io), 31 P2.7/A15 (io), 32 ~{PSEN} (out), 33 ALE/~{PROG} (io), 34 NIC, 35 ~{EA}/VPP (in), 36 P0.7/AD7 (io), 37 P0.6/AD6 (io), 38 P0.5/AD5 (io), 39 P0.4/AD4 (io), 40 P0.3/AD3 (io), 41 P0.2/AD2 (io), 42 P0.1/AD1 (io), 43 P0.0/AD0 (io), 44 VCC (power)

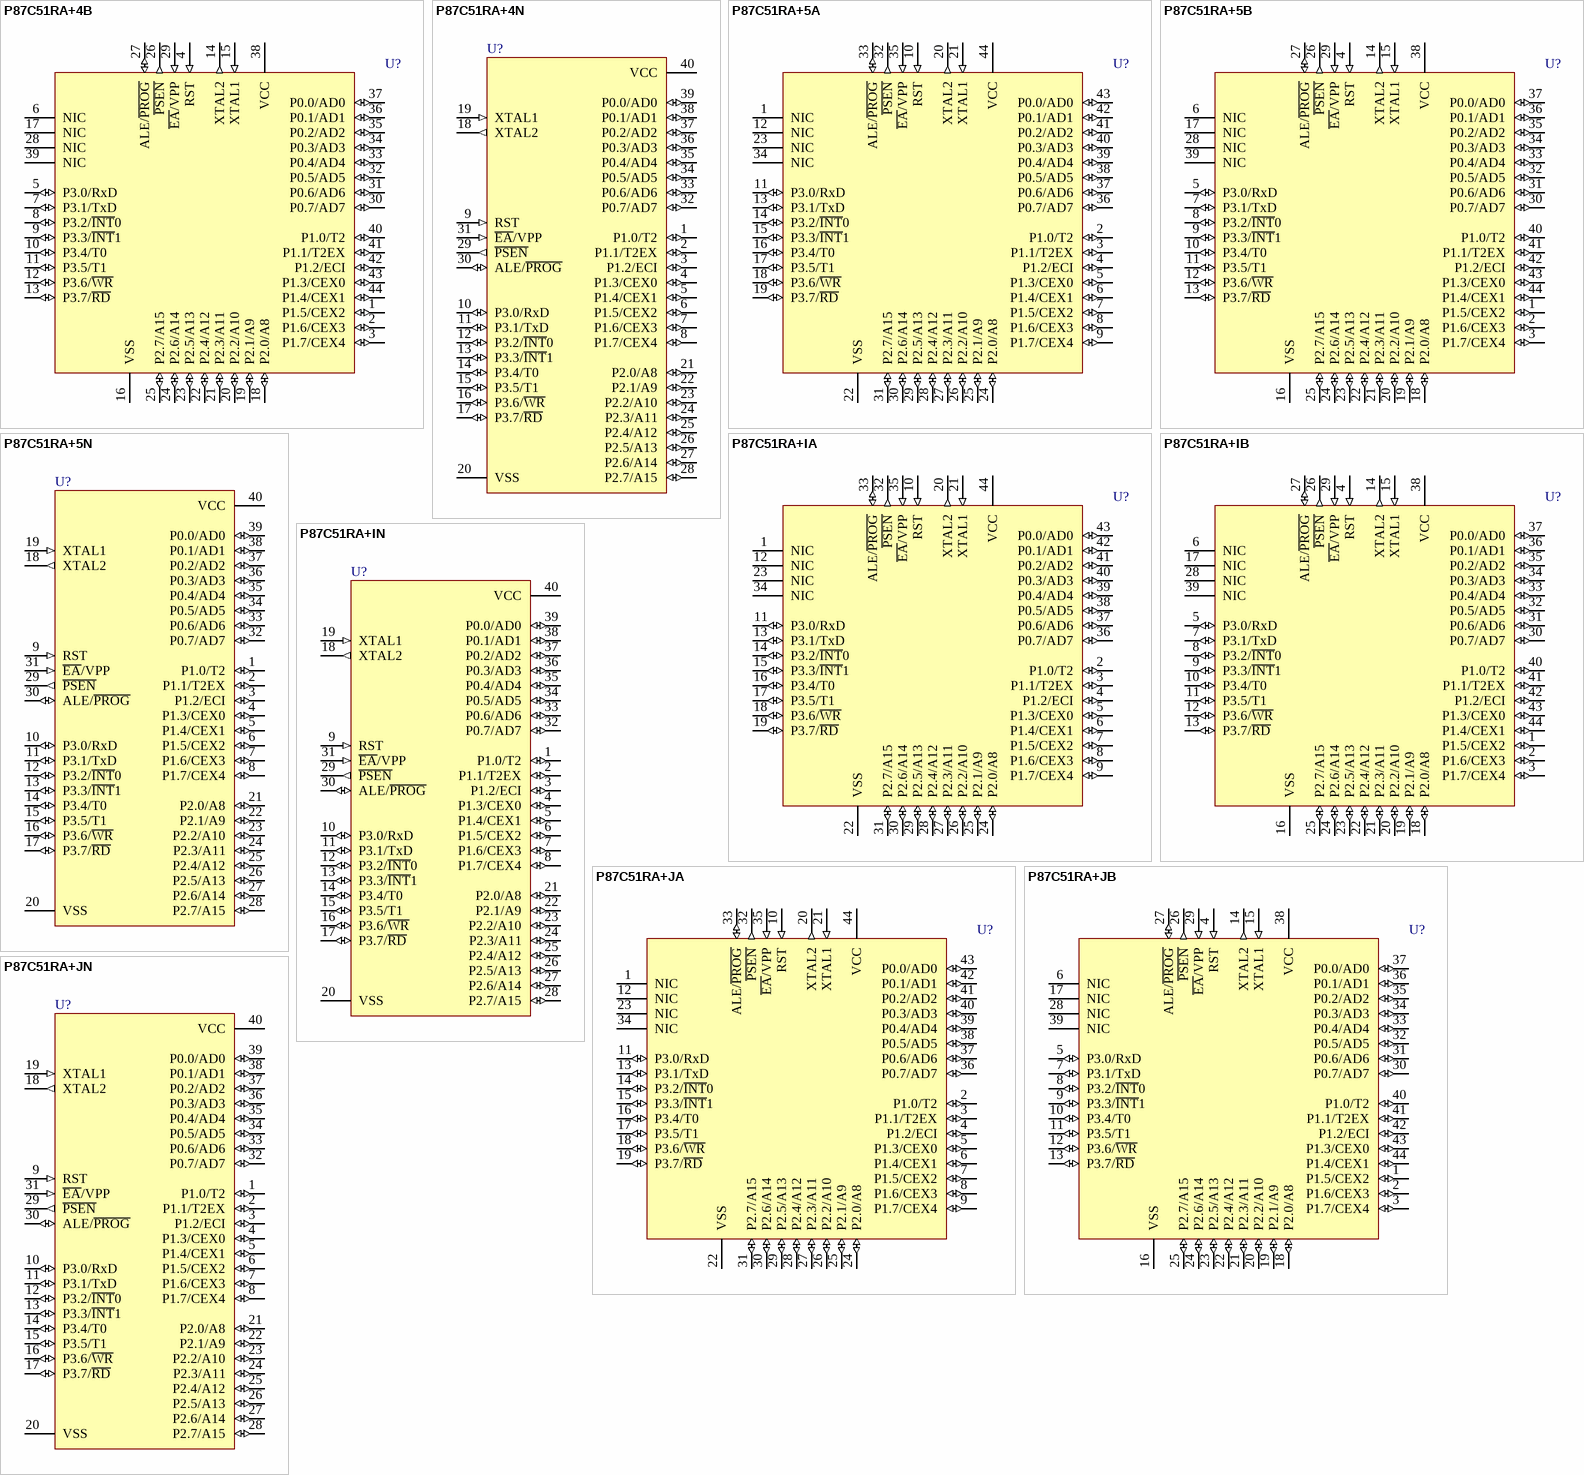
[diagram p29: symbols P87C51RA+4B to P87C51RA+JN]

## P87C51RA+4B
designator U?
80C51 8-Bit Microcontroller Family: 512 B RAM, 8 kB OTP, 2.7V-5.5V, Low Power, High Speed
footprint SOT307-2_N (QFP, 44-Leads, Body 10x10mm, Pitch 0.8mm, IPC Medium Density)
footprint SOT307-2_L (QFP, 44-Leads, Body 10x10mm, Pitch 0.8mm, IPC High Density)
footprint SOT307-2_M (QFP, 44-Leads, Body 10x10mm, Pitch 0.8mm, IPC Low Density)
pins: 1 P1.5/CEX2 (io), 2 P1.6/CEX3 (io), 3 P1.7/CEX4 (io), 4 RST (in), 5 P3.0/RxD (io), 6 NIC, 7 P3.1/TxD (io), 8 P3.2/~{INT}0 (io), 9 P3.3/~{INT}1 (io), 10 P3.4/T0 (io), 11 P3.5/T1 (io), 12 P3.6/~{WR} (io), 13 P3.7/~{RD} (io), 14 XTAL2 (out), 15 XTAL1 (in), 16 VSS (power), 17 NIC, 18 P2.0/A8 (io), 19 P2.1/A9 (io), 20 P2.2/A10 (io), 21 P2.3/A11 (io), 22 P2.4/A12 (io), 23 P2.5/A13 (io), 24 P2.6/A14 (io), 25 P2.7/A15 (io), 26 ~{PSEN} (out), 27 ALE/~{PROG} (io), 28 NIC, 29 ~{EA}/VPP (in), 30 P0.7/AD7 (io), 31 P0.6/AD6 (io), 32 P0.5/AD5 (io), 33 P0.4/AD4 (io), 34 P0.3/AD3 (io), 35 P0.2/AD2 (io), 36 P0.1/AD1 (io), 37 P0.0/AD0 (io), 38 VCC (power), 39 NIC, 40 P1.0/T2 (io), 41 P1.1/T2EX (io), 42 P1.2/ECI (io), 43 P1.3/CEX0 (io), 44 P1.4/CEX1 (io)

## P87C51RA+4N
designator U?
80C51 8-Bit Microcontroller Family: 512 B RAM, 8 kB OTP, 2.7V-5.5V, Low Power, High Speed
footprint SOT129-1 (DIP, Plastic; 40 Leads; Row Spacing 15.24 mm; Pitch 2.54 mm)
pins: 1 P1.0/T2 (io), 2 P1.1/T2EX (io), 3 P1.2/ECI (io), 4 P1.3/CEX0 (io), 5 P1.4/CEX1 (io), 6 P1.5/CEX2 (io), 7 P1.6/CEX3 (io), 8 P1.7/CEX4 (io), 9 RST (in), 10 P3.0/RxD (io), 11 P3.1/TxD (io), 12 P3.2/~{INT}0 (io), 13 P3.3/~{INT}1 (io), 14 P3.4/T0 (io), 15 P3.5/T1 (io), 16 P3.6/~{WR} (io), 17 P3.7/~{RD} (io), 18 XTAL2 (out), 19 XTAL1 (in), 20 VSS (power), 21 P2.0/A8 (io), 22 P2.1/A9 (io), 23 P2.2/A10 (io), 24 P2.3/A11 (io), 25 P2.4/A12 (io), 26 P2.5/A13 (io), 27 P2.6/A14 (io), 28 P2.7/A15 (io), 29 ~{PSEN} (out), 30 ALE/~{PROG} (io), 31 ~{EA}/VPP (in), 32 P0.7/AD7 (io), 33 P0.6/AD6 (io), 34 P0.5/AD5 (io), 35 P0.4/AD4 (io), 36 P0.3/AD3 (io), 37 P0.2/AD2 (io), 38 P0.1/AD1 (io), 39 P0.0/AD0 (io), 40 VCC (power)

## P87C51RA+5A
designator U?
80C51 8-Bit Microcontroller Family: 512 B RAM, 8 kB OTP, 2.7V-5.5V, Low Power, High Speed
footprint SOT187-2_N (Leaded Chip Carrier, 44-Leads, Body 16.6x16.6mm, Pitch 1.27mm, IPC Medium Density)
footprint SOT187-2_L (Leaded Chip Carrier, 44-Leads, Body 16.6x16.6mm, Pitch 1.27mm, IPC High Density)
footprint SOT187-2_M (Leaded Chip Carrier, 44-Leads, Body 16.6x16.6mm, Pitch 1.27mm, IPC Low Density)
pins: 1 NIC, 2 P1.0/T2 (io), 3 P1.1/T2EX (io), 4 P1.2/ECI (io), 5 P1.3/CEX0 (io), 6 P1.4/CEX1 (io), 7 P1.5/CEX2 (io), 8 P1.6/CEX3 (io), 9 P1.7/CEX4 (io), 10 RST (in), 11 P3.0/RxD (io), 12 NIC, 13 P3.1/TxD (io), 14 P3.2/~{INT}0 (io), 15 P3.3/~{INT}1 (io), 16 P3.4/T0 (io), 17 P3.5/T1 (io), 18 P3.6/~{WR} (io), 19 P3.7/~{RD} (io), 20 XTAL2 (out), 21 XTAL1 (in), 22 VSS (power), 23 NIC, 24 P2.0/A8 (io), 25 P2.1/A9 (io), 26 P2.2/A10 (io), 27 P2.3/A11 (io), 28 P2.4/A12 (io), 29 P2.5/A13 (io), 30 P2.6/A14 (io), 31 P2.7/A15 (io), 32 ~{PSEN} (out), 33 ALE/~{PROG} (io), 34 NIC, 35 ~{EA}/VPP (in), 36 P0.7/AD7 (io), 37 P0.6/AD6 (io), 38 P0.5/AD5 (io), 39 P0.4/AD4 (io), 40 P0.3/AD3 (io), 41 P0.2/AD2 (io), 42 P0.1/AD1 (io), 43 P0.0/AD0 (io), 44 VCC (power)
